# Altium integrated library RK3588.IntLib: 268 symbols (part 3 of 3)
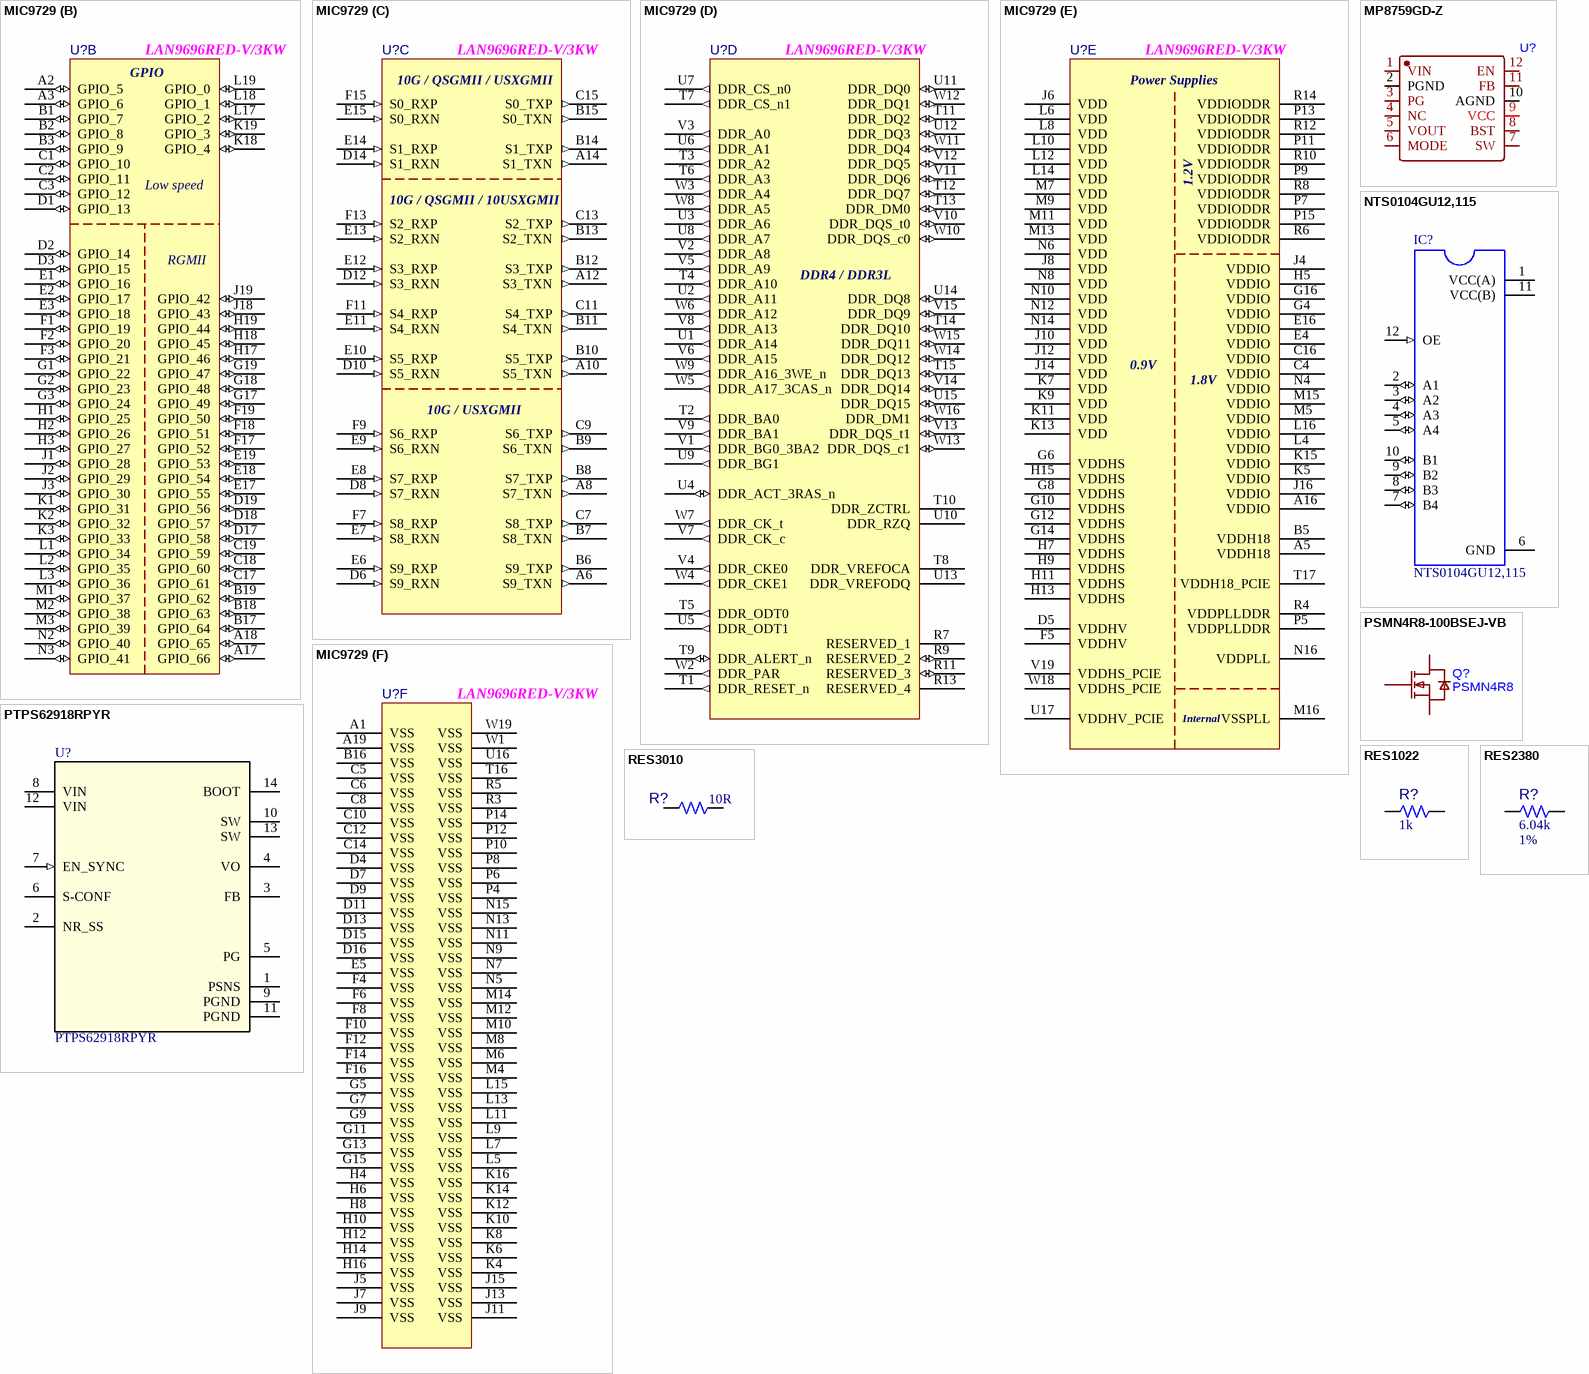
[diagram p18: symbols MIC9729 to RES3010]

## PTPS62918RPYR
designator U?
17V VIN, 8A low-noise low-ripple buck converter with integrated ferrite-bead filter compensation 14-VQFN-HR -40 to 150; Manufacturer_Name: Texas Instruments
footprint RPY0014A-MFG
pins: 1 PSNS, 2 NR_SS, 3 FB, 4 VO, 5 PG (oc), 6 S-CONF, 7 EN_SYNC (in), 8 VIN (power), 9 PGND (power), 10 SW, 11 PGND (power), 12 VIN (power), 13 SW, 14 BOOT

## RES1022
designator R?, comment value 1k  (hidden comment: Resistor)
Manufacturer 1: Panasonic; Manufacturer Part Number 1: ERJ-2RKF1001X; MCHP-ID: RES1022; Tolerance: 1%; Description_: RES TKF 1k 1% 1/10W SMD 0402; Dev Tools Status: Production; Voltage: 50V; Power: 1/10W; Populated: YES; Owner: Tad Ahlvers; Temperature Coefficient: 100ppm/C
footprint RES_C_0402
pins: 1, 2
2 alternate drawings of the same symbol

## RES2380
designator R?, comment value 6.04k  Tolerance: 1%  (hidden comment: Resistor)
Manufacturer 1: Panasonic Electronic Components; Manufacturer Part Number 1: ERJ-2RKF6041X; MCHP-ID: RES2380; Description_: RES TKF 6.04k 1% 1/10W SMD 0402 AEC-Q200; Dev Tools Status: Production; Circuit Type: Isolated; Power: 1/10W; Owner: Steve Dziaba; Populated: YES; Restricted Sourcing: No
footprint RES_C_0402
pins: 1, 2

## RES3010
designator R?, comment value 10R  (hidden comment: Resistor)
Manufacturer 1: Vishay Dale; Manufacturer Part Number 1: CRCW040210R0FKEDC; MCHP-ID: RES3010; Description_: RES TKF 10R 1% 1/16W SMD 0402; Dev Tools Status: Production; Populated: YES; Power: 1/16W; Owner: Balaji Narayana; Tolerance: 1%; Temperature Coefficient: 100ppm/C; Restricted Sourcing: No
footprint RES_C_0402
pins: 1, 2
2 alternate drawings of the same symbol

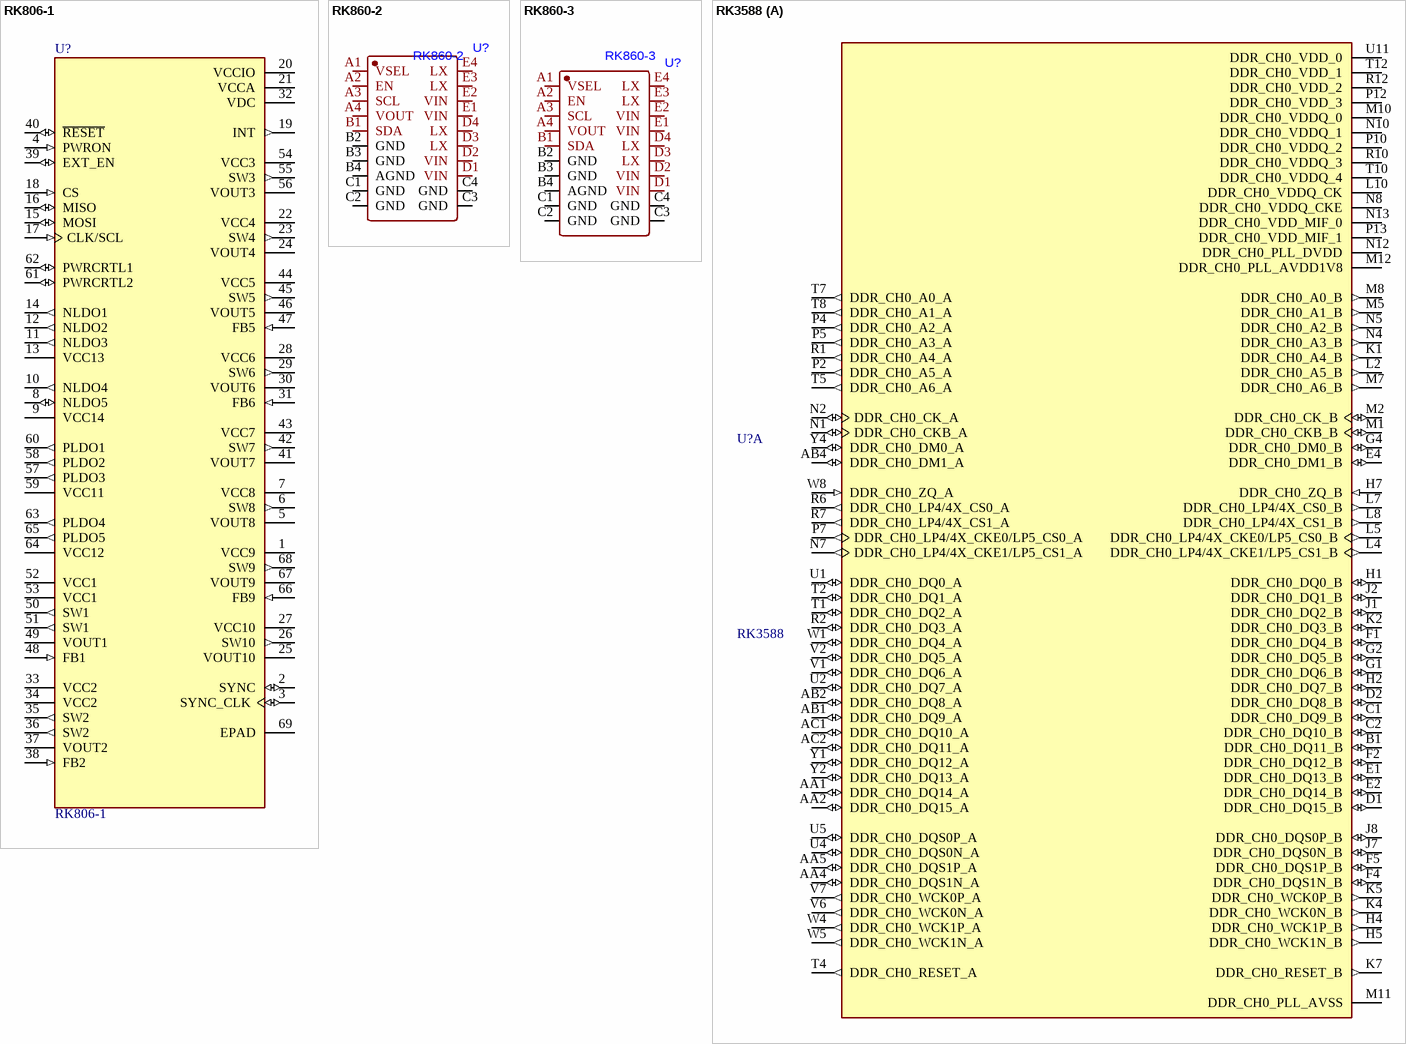
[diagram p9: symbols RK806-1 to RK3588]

## RK806-1
designator U?
RK806-1 Power Management IC; MF: rockchip
footprint QFN35P700X700X90-69N
pins: 1 VCC9 (power), 2 SYNC (io), 3 SYNC_CLK (io), 4 PWRON (in), 5 VOUT8 (power), 6 SW8 (out), 7 VCC8 (power), 8 NLDO5 (io), 9 VCC14 (power), 10 NLDO4 (out), 11 NLDO3 (out), 12 NLDO2 (out), 13 VCC13 (power), 14 NLDO1 (out), 15 MOSI (io), 16 MISO (io), 17 CLK/SCL (in), 18 CS (in), 19 INT (out), 20 VCCIO (power), 21 VCCA (power), 22 VCC4 (power), 23 SW4 (out), 24 VOUT4 (power), 25 VOUT10 (power), 26 SW10 (out), 27 VCC10 (power), 28 VCC6 (power), 29 SW6 (out), 30 VOUT6 (power), 31 FB6 (in), 32 VDC (power), 33 VCC2 (power), 34 VCC2 (power), 35 SW2 (out), 36 SW2 (out), 37 VOUT2 (power), 38 FB2 (in), 39 EXT_EN (io), 40 ~{RESET} (io), 41 VOUT7 (power), 42 SW7 (out), 43 VCC7 (power), 44 VCC5 (power), 45 SW5 (out), 46 VOUT5 (power), 47 FB5 (in), 48 FB1 (in), 49 VOUT1 (power), 50 SW1 (out), 51 SW1 (out), 52 VCC1 (power), 53 VCC1 (power), 54 VCC3 (power), 55 SW3 (out), 56 VOUT3 (power), 57 PLDO3 (out), 58 PLDO2 (out), 59 VCC11 (power), 60 PLDO1 (out), 61 PWRCRTL2 (io), 62 PWRCRTL1 (io), 63 PLDO4 (out), 64 VCC12 (power), 65 PLDO5 (out), 66 FB9 (in), 67 VOUT9 (power), 68 SW9 (out), 69 EPAD

## RK860-2
designator U?
footprint WLCSP-20_L2.0-W1.6-R5-C4-P0.40-TL
pins: A1 VSEL, A2 EN, A3 SCL, A4 VOUT, B1 SDA, B2 GND, B3 GND, B4 AGND, C1 GND, C2 GND, C3 GND, C4 GND, D1 VIN, D2 VIN, D3 LX, D4 LX, E1 VIN, E2 VIN, E3 LX, E4 LX

## RK860-3
designator U?
footprint WLCSP-20_L2.0-W1.6-R5-C4-P0.40-TL
pins: A1 VSEL, A2 EN, A3 SCL, A4 VOUT, B1 SDA, B2 GND, B3 GND, B4 AGND, C1 GND, C2 GND, C3 GND, C4 GND, D1 VIN, D2 VIN, D3 LX, D4 LX, E1 VIN, E2 VIN, E3 LX, E4 LX

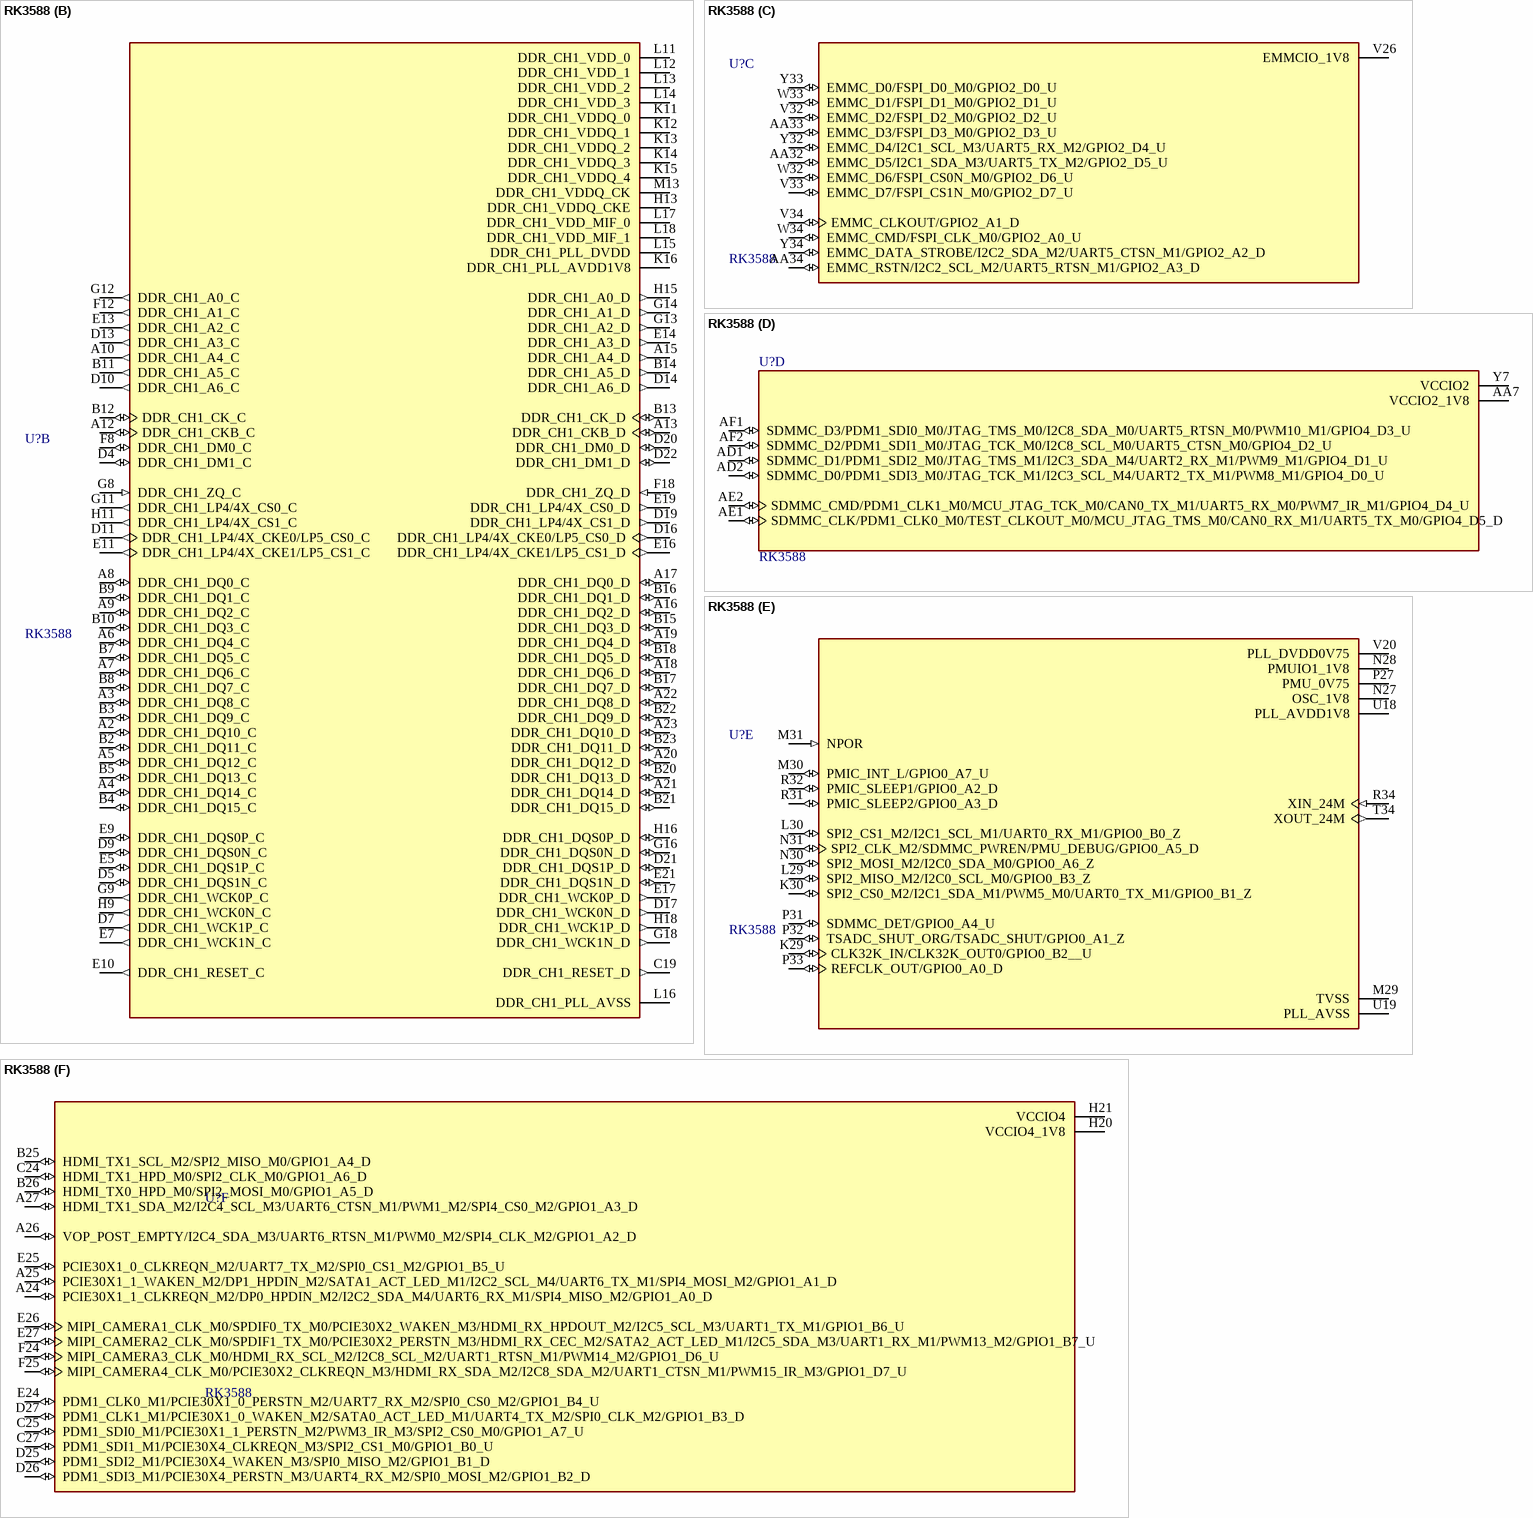
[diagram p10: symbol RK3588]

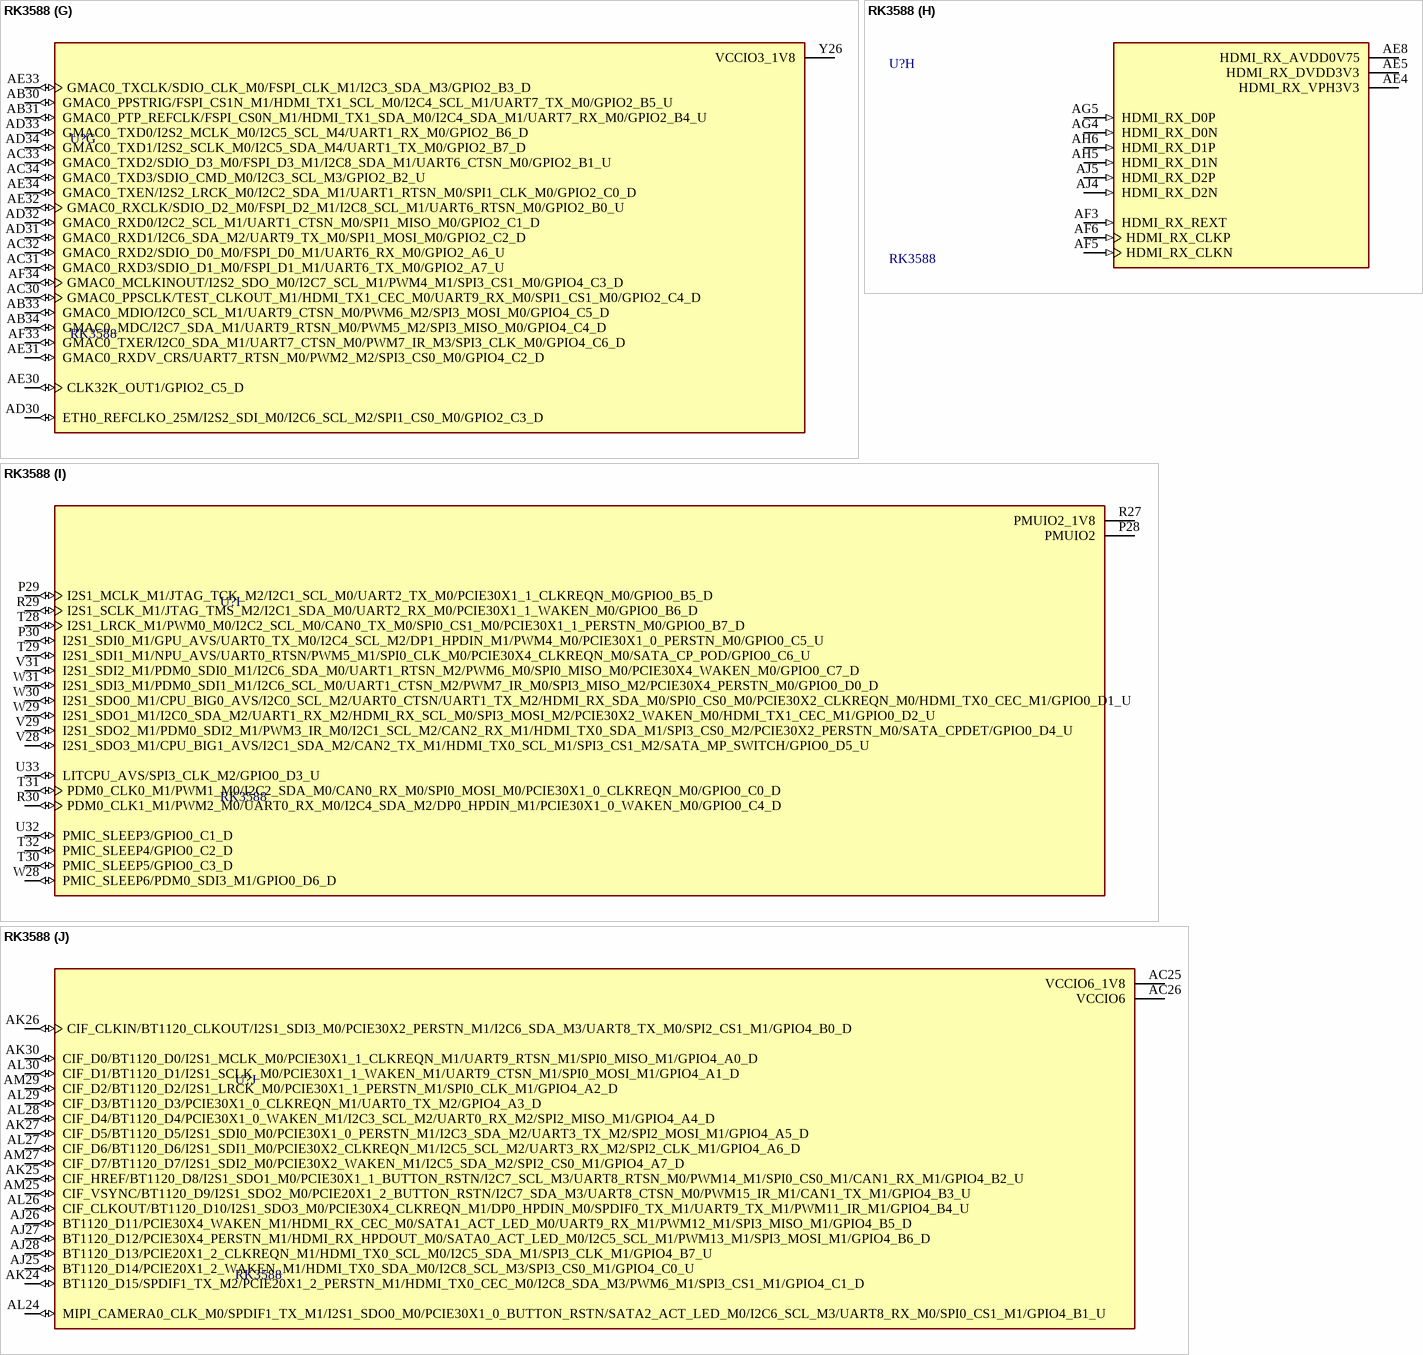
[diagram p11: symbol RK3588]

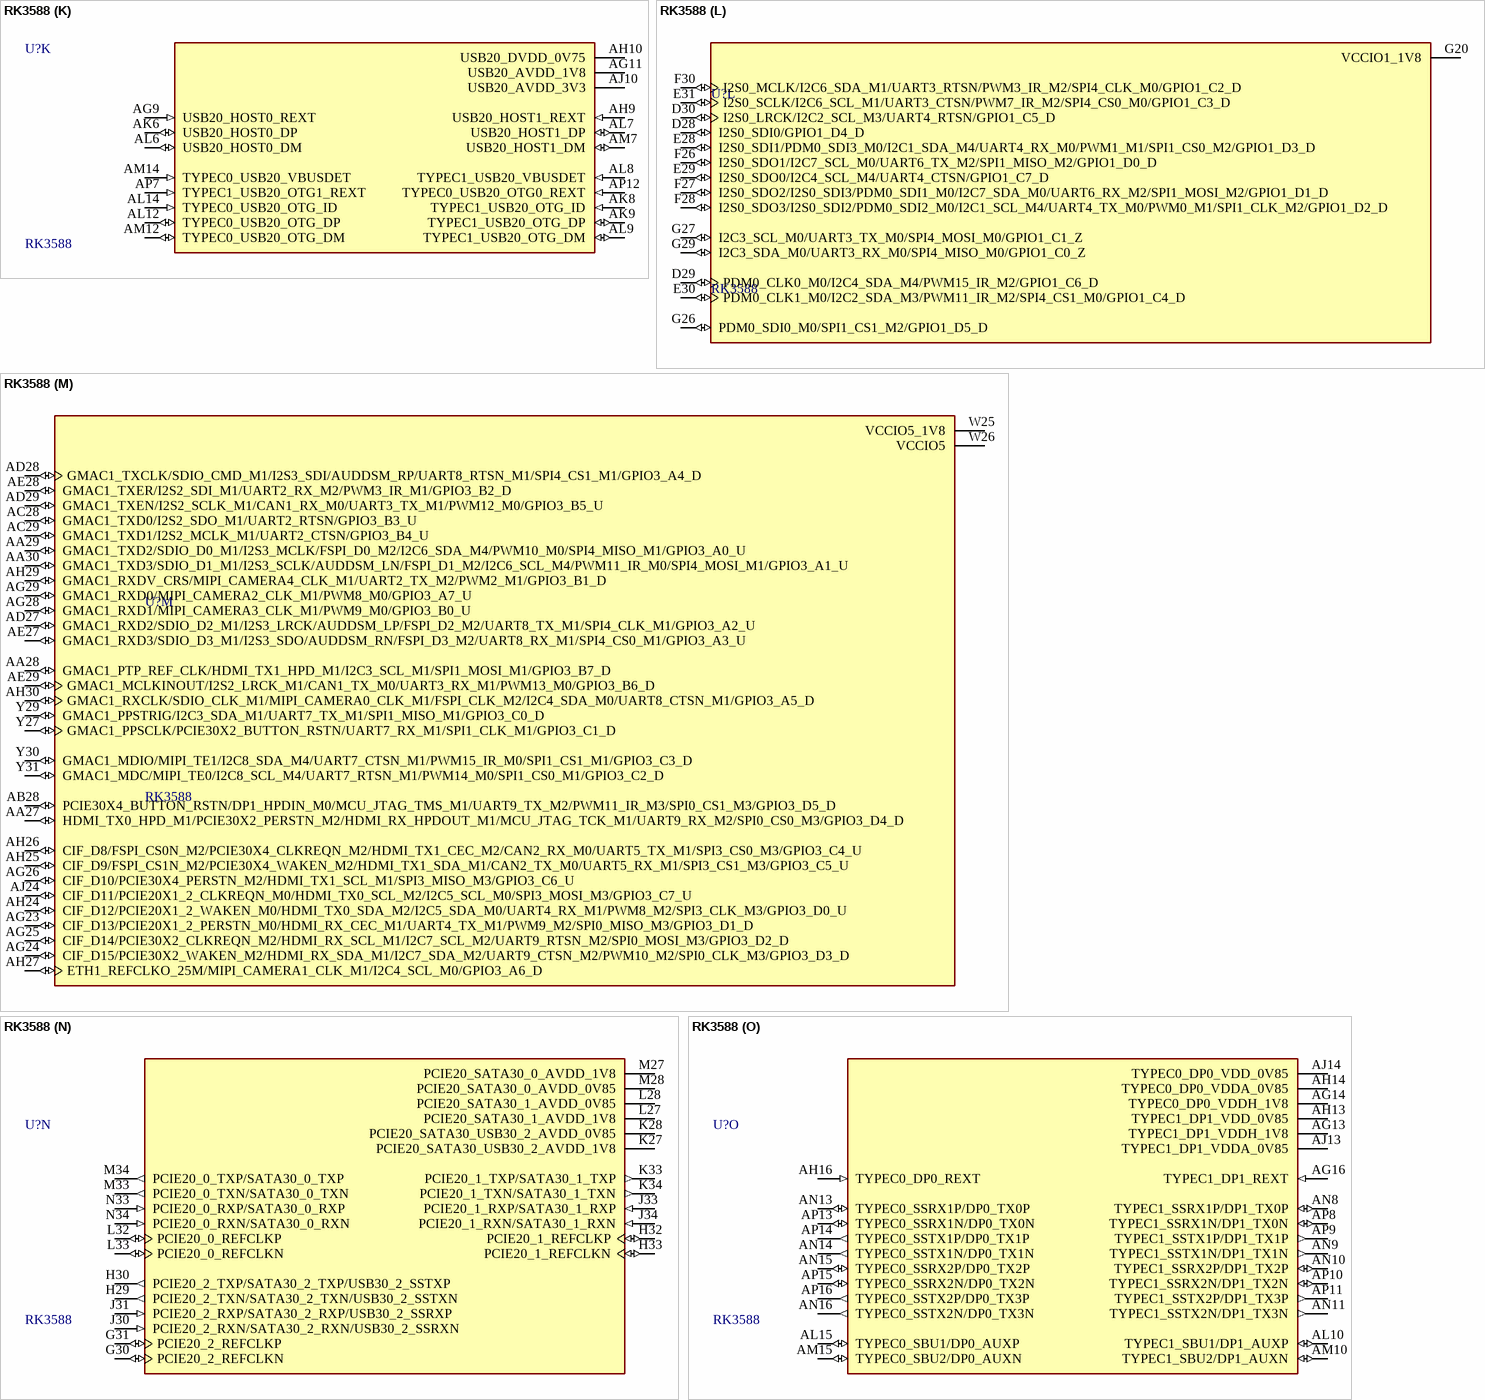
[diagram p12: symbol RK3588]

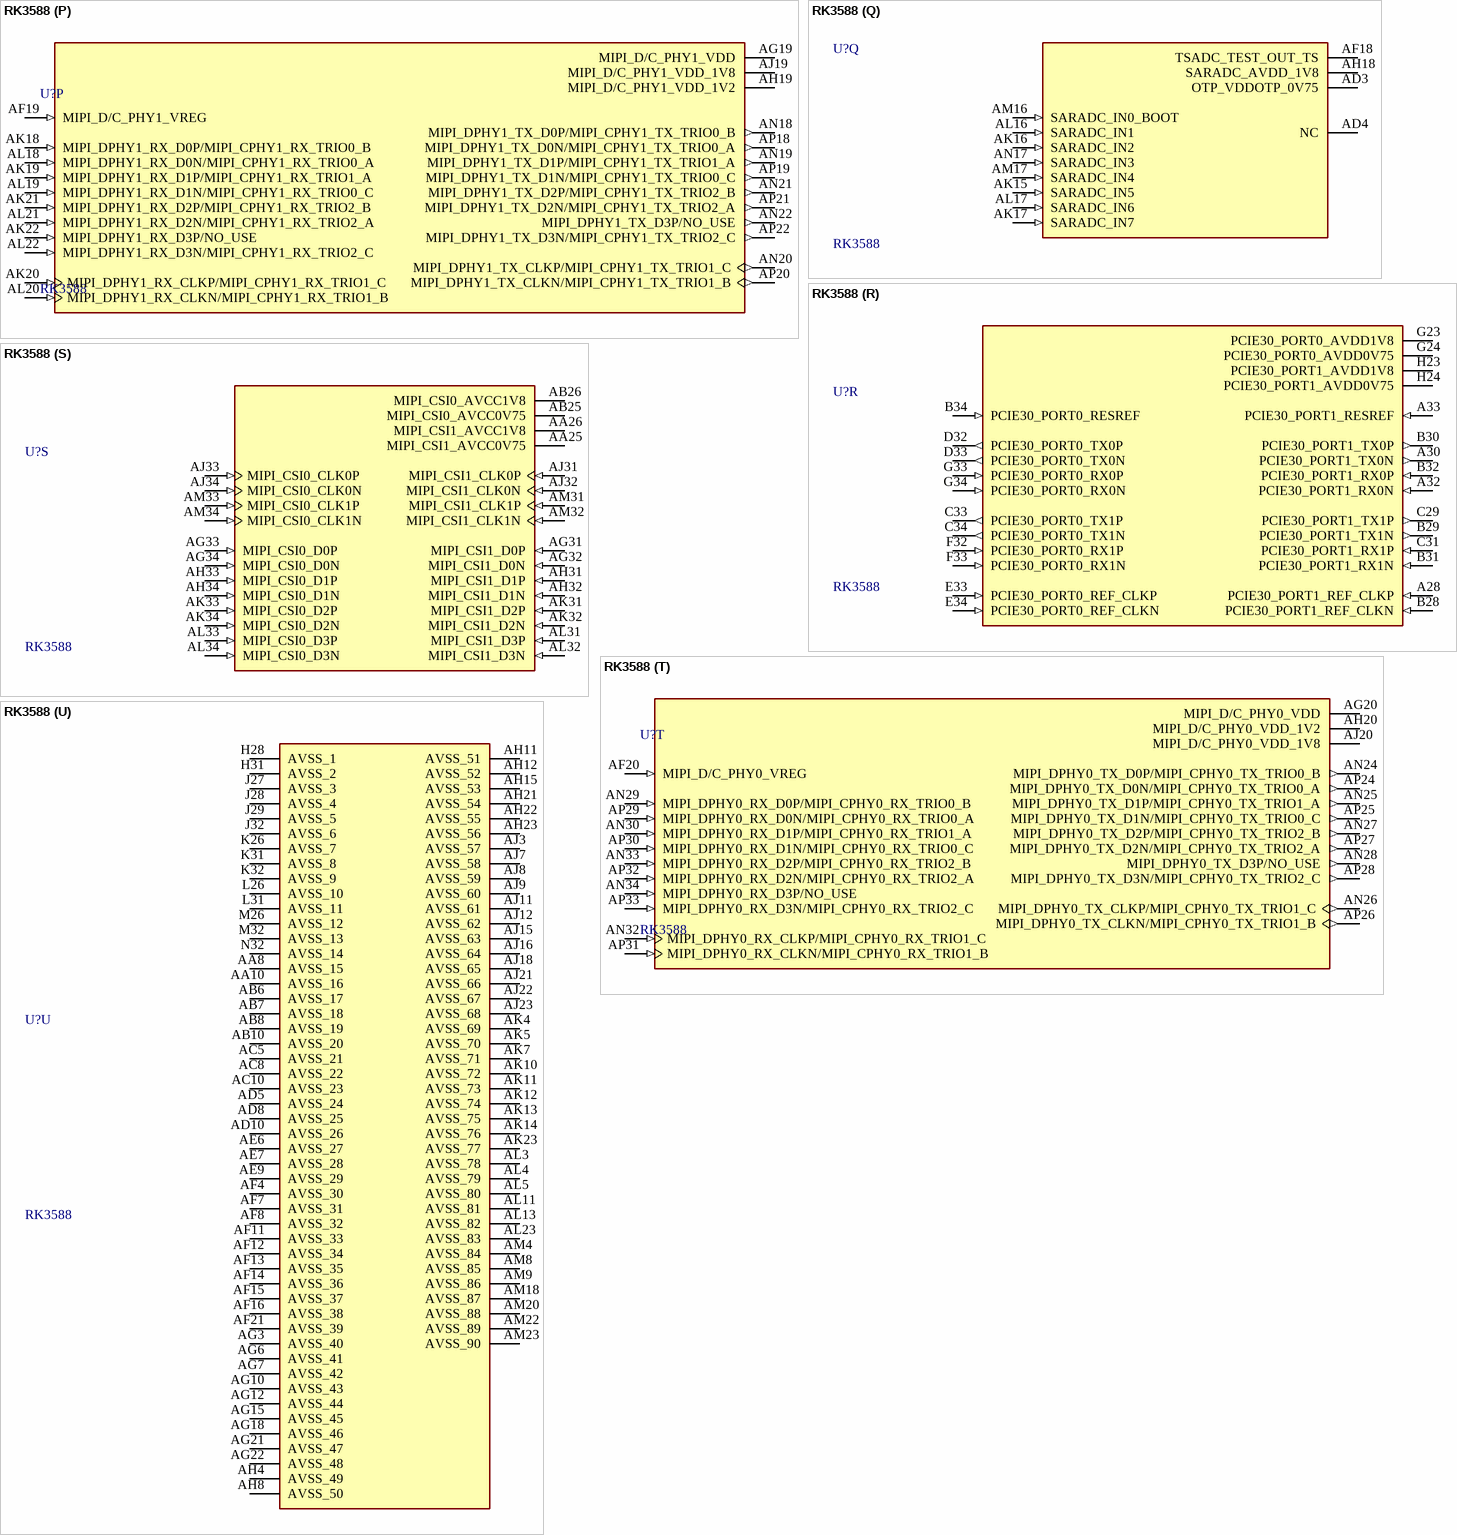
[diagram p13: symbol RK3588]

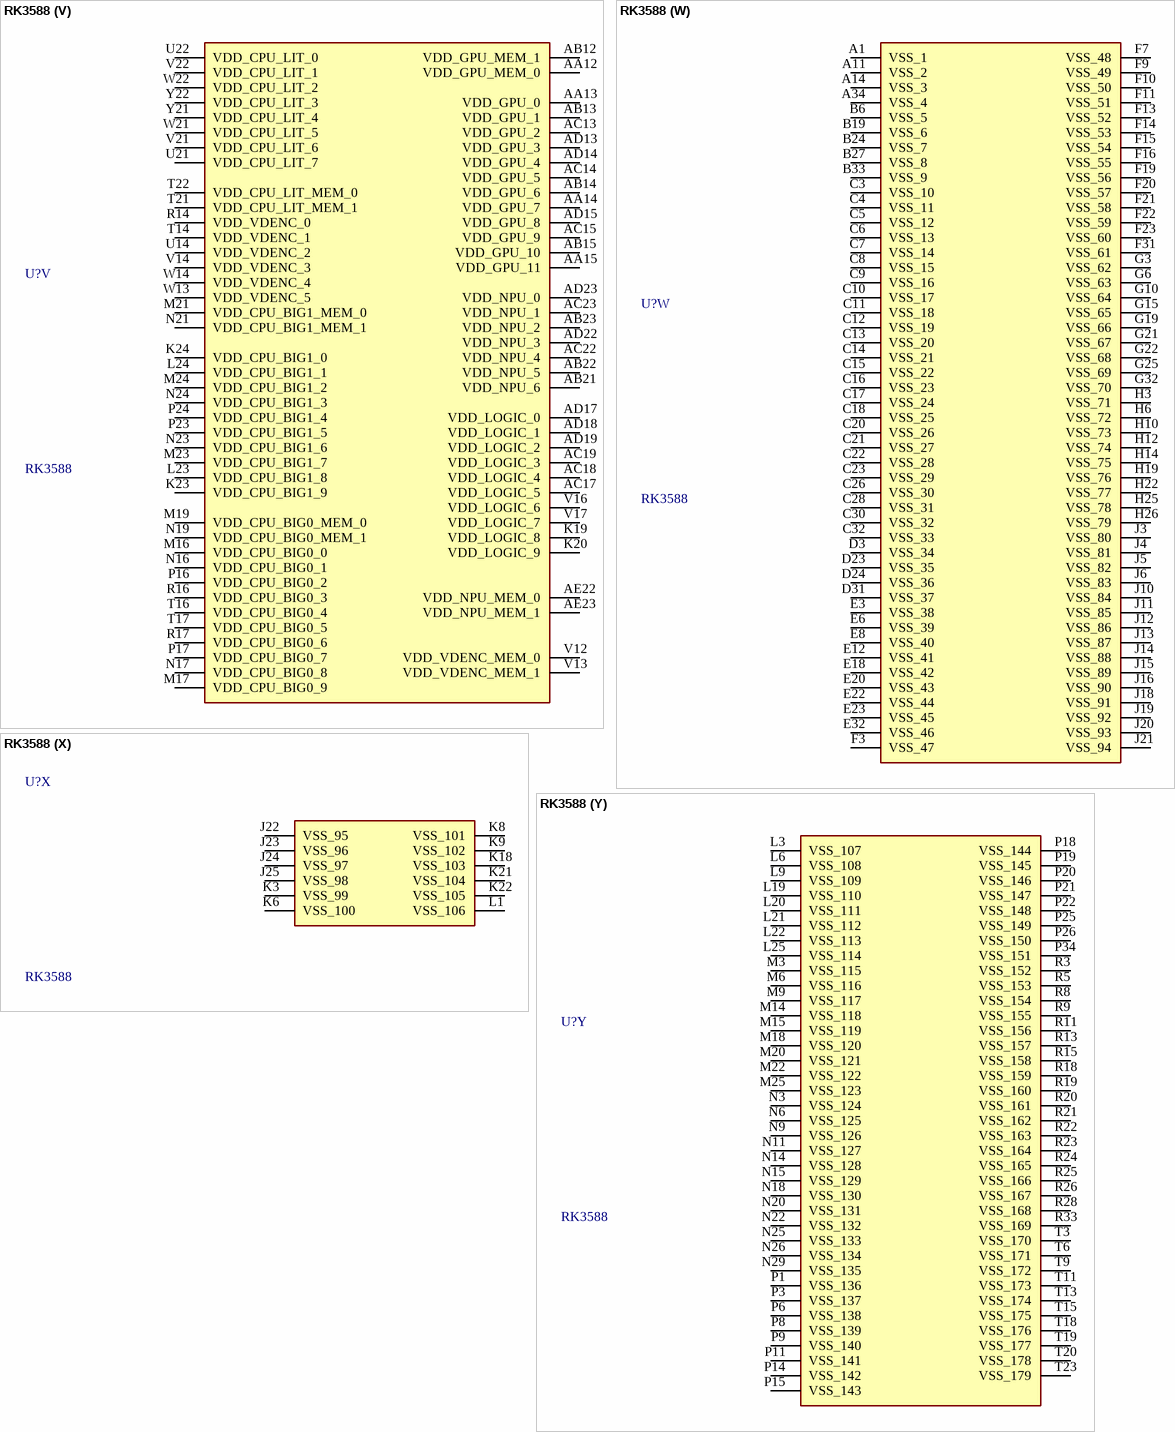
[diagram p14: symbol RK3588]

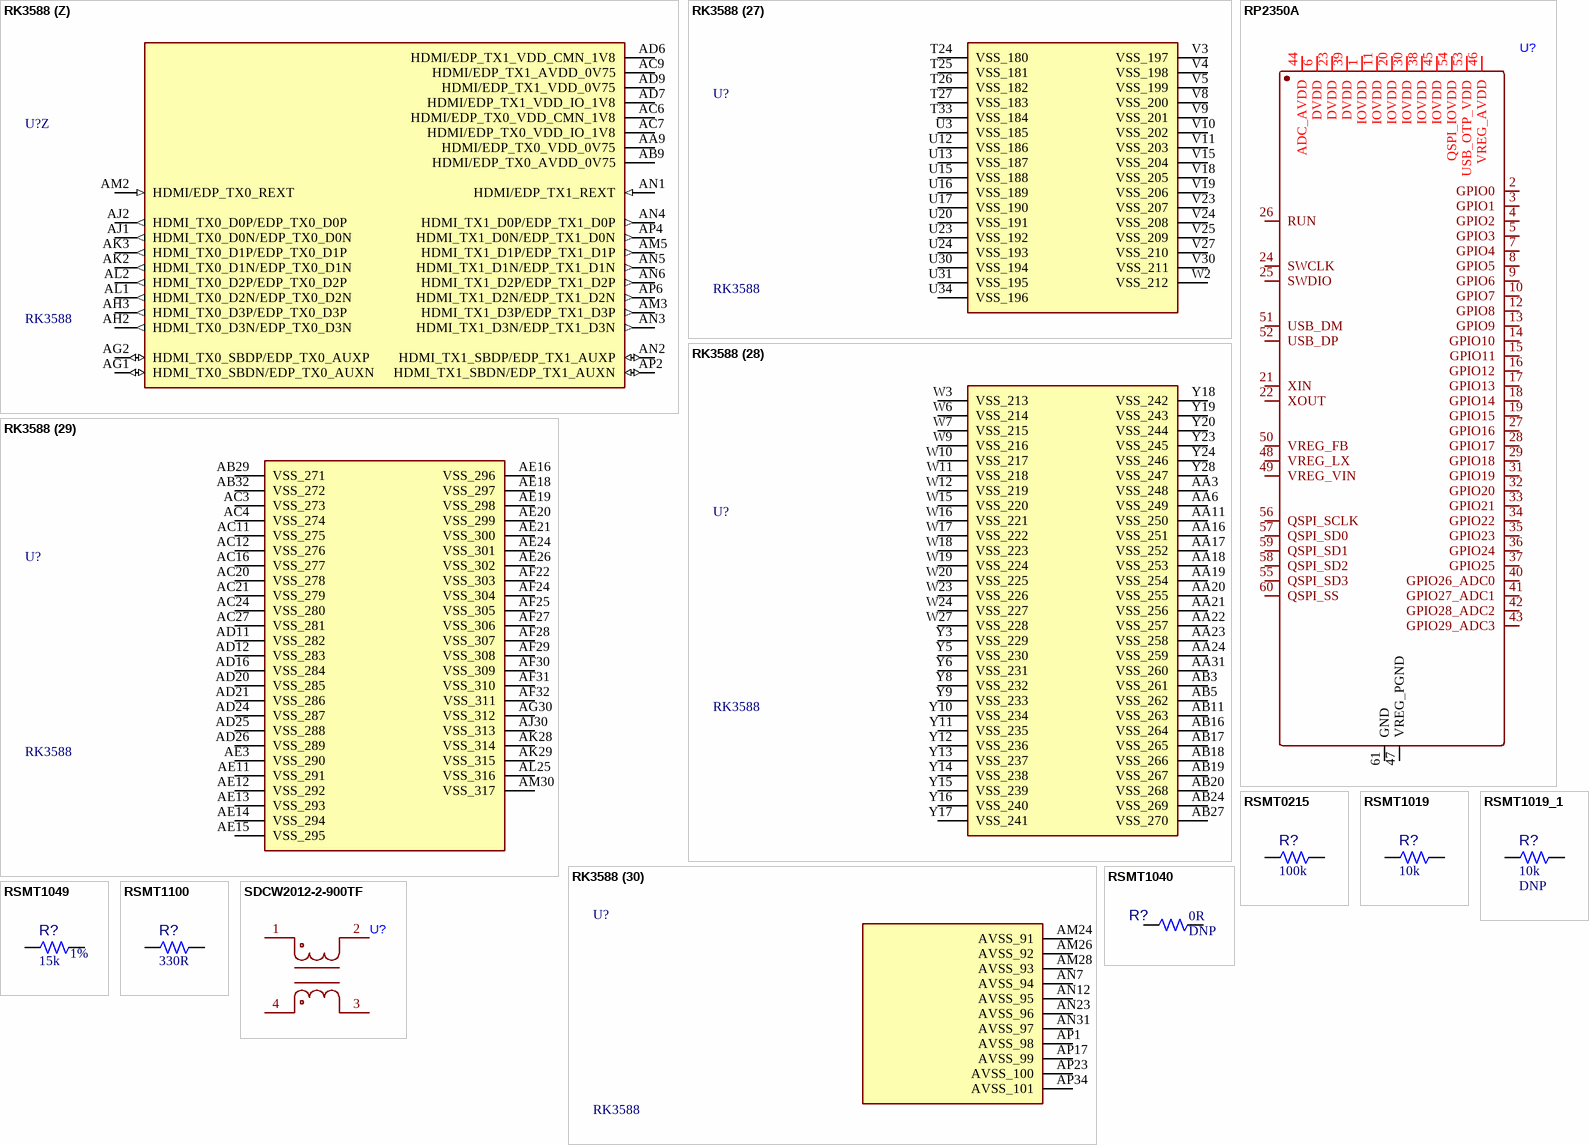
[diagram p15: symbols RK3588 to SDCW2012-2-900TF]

## RK3588
designator U?
low power, high performance processor; MF: Fuzhou Rockchip Electronics Co
footprint BGA1088C65P34X34_2300X2300X204N
part A pins: AA1 DDR_CH0_DQ14_A (io), AA2 DDR_CH0_DQ15_A (io), AA4 DDR_CH0_DQS1N_A (io), AA5 DDR_CH0_DQS1P_A (io), AB1 DDR_CH0_DQ9_A (io), AB2 DDR_CH0_DQ8_A (io), AB4 DDR_CH0_DM1_A (io), AC1 DDR_CH0_DQ10_A (io), AC2 DDR_CH0_DQ11_A (io), B1 DDR_CH0_DQ11_B (io), C1 DDR_CH0_DQ9_B (io), C2 DDR_CH0_DQ10_B (io), D1 DDR_CH0_DQ15_B (io), D2 DDR_CH0_DQ8_B (io), E1 DDR_CH0_DQ13_B (io), E2 DDR_CH0_DQ14_B (io), E4 DDR_CH0_DM1_B (io), F1 DDR_CH0_DQ4_B (io), F2 DDR_CH0_DQ12_B (io), F4 DDR_CH0_DQS1N_B (io), F5 DDR_CH0_DQS1P_B (io), G1 DDR_CH0_DQ6_B (io), G2 DDR_CH0_DQ5_B (io), G4 DDR_CH0_DM0_B (io), H1 DDR_CH0_DQ0_B (io), H2 DDR_CH0_DQ7_B (io), H4 DDR_CH0_WCK1P_B (out), H5 DDR_CH0_WCK1N_B (out), H7 DDR_CH0_ZQ_B (in), J1 DDR_CH0_DQ2_B (io), J2 DDR_CH0_DQ1_B (io), J7 DDR_CH0_DQS0N_B (io), J8 DDR_CH0_DQS0P_B (io), K1 DDR_CH0_A4_B (out), K2 DDR_CH0_DQ3_B (io), K4 DDR_CH0_WCK0N_B (out), K5 DDR_CH0_WCK0P_B (out), K7 DDR_CH0_RESET_B (out), L2 DDR_CH0_A5_B (out), L4 DDR_CH0_LP4/4X_CKE1/LP5_CS1_B (out), L5 DDR_CH0_LP4/4X_CKE0/LP5_CS0_B (out), L7 DDR_CH0_LP4/4X_CS0_B (out), L8 DDR_CH0_LP4/4X_CS1_B (out), L10 DDR_CH0_VDDQ_CK (power), M1 DDR_CH0_CKB_B (io), M2 DDR_CH0_CK_B (io), M5 DDR_CH0_A1_B (out), M7 DDR_CH0_A6_B (out), M8 DDR_CH0_A0_B (out), M10 DDR_CH0_VDDQ_0 (power), M11 DDR_CH0_PLL_AVSS (power), M12 DDR_CH0_PLL_AVDD1V8 (power), N1 DDR_CH0_CKB_A (io), N2 DDR_CH0_CK_A (io), N4 DDR_CH0_A3_B (out), N5 DDR_CH0_A2_B (out), N7 DDR_CH0_LP4/4X_CKE1/LP5_CS1_A (out), N8 DDR_CH0_VDDQ_CKE (power), N10 DDR_CH0_VDDQ_1 (power), N12 DDR_CH0_PLL_DVDD (power), N13 DDR_CH0_VDD_MIF_0 (power), P2 DDR_CH0_A5_A (out), P4 DDR_CH0_A2_A (out), P5 DDR_CH0_A3_A (out), P7 DDR_CH0_LP4/4X_CKE0/LP5_CS0_A (out), P10 DDR_CH0_VDDQ_2 (power), P12 DDR_CH0_VDD_3 (power), P13 DDR_CH0_VDD_MIF_1 (power), R1 DDR_CH0_A4_A (out), R2 DDR_CH0_DQ3_A (io), R6 DDR_CH0_LP4/4X_CS0_A (out), R7 DDR_CH0_LP4/4X_CS1_A (out), R10 DDR_CH0_VDDQ_3 (power), R12 DDR_CH0_VDD_2 (power), T1 DDR_CH0_DQ2_A (io), T2 DDR_CH0_DQ1_A (io), T4 DDR_CH0_RESET_A (out), T5 DDR_CH0_A6_A (out), T7 DDR_CH0_A0_A (out), T8 DDR_CH0_A1_A (out), T10 DDR_CH0_VDDQ_4 (power), T12 DDR_CH0_VDD_1 (power), U1 DDR_CH0_DQ0_A (io), U2 DDR_CH0_DQ7_A (io), U4 DDR_CH0_DQS0N_A (io), U5 DDR_CH0_DQS0P_A (io), U11 DDR_CH0_VDD_0 (power), V1 DDR_CH0_DQ6_A (io), V2 DDR_CH0_DQ5_A (io), V6 DDR_CH0_WCK0N_A (out), V7 DDR_CH0_WCK0P_A (out), W1 DDR_CH0_DQ4_A (io), W4 DDR_CH0_WCK1P_A (out), W5 DDR_CH0_WCK1N_A (out), W8 DDR_CH0_ZQ_A (in), Y1 DDR_CH0_DQ12_A (io), Y2 DDR_CH0_DQ13_A (io), Y4 DDR_CH0_DM0_A (io)
part B pins: A2 DDR_CH1_DQ10_C (io), A3 DDR_CH1_DQ8_C (io), A4 DDR_CH1_DQ14_C (io), A5 DDR_CH1_DQ12_C (io), A6 DDR_CH1_DQ4_C (io), A7 DDR_CH1_DQ6_C (io), A8 DDR_CH1_DQ0_C (io), A9 DDR_CH1_DQ2_C (io), A10 DDR_CH1_A4_C (out), A12 DDR_CH1_CKB_C (io), A13 DDR_CH1_CKB_D (io), A15 DDR_CH1_A4_D (out), A16 DDR_CH1_DQ2_D (io), A17 DDR_CH1_DQ0_D (io), A18 DDR_CH1_DQ6_D (io), A19 DDR_CH1_DQ4_D (io), A20 DDR_CH1_DQ12_D (io), A21 DDR_CH1_DQ14_D (io), A22 DDR_CH1_DQ8_D (io), A23 DDR_CH1_DQ10_D (io), B2 DDR_CH1_DQ11_C (io), B3 DDR_CH1_DQ9_C (io), B4 DDR_CH1_DQ15_C (io), B5 DDR_CH1_DQ13_C (io), B7 DDR_CH1_DQ5_C (io), B8 DDR_CH1_DQ7_C (io), B9 DDR_CH1_DQ1_C (io), B10 DDR_CH1_DQ3_C (io), B11 DDR_CH1_A5_C (out), B12 DDR_CH1_CK_C (io), B13 DDR_CH1_CK_D (io), B14 DDR_CH1_A5_D (out), B15 DDR_CH1_DQ3_D (io), B16 DDR_CH1_DQ1_D (io), B17 DDR_CH1_DQ7_D (io), B18 DDR_CH1_DQ5_D (io), B20 DDR_CH1_DQ13_D (io), B21 DDR_CH1_DQ15_D (io), B22 DDR_CH1_DQ9_D (io), B23 DDR_CH1_DQ11_D (io), C19 DDR_CH1_RESET_D (out), D4 DDR_CH1_DM1_C (io), D5 DDR_CH1_DQS1N_C (io), D7 DDR_CH1_WCK1P_C (out), D9 DDR_CH1_DQS0N_C (io), D10 DDR_CH1_A6_C (out), D11 DDR_CH1_LP4/4X_CKE0/LP5_CS0_C (out), D13 DDR_CH1_A3_C (out), D14 DDR_CH1_A6_D (out), D16 DDR_CH1_LP4/4X_CKE0/LP5_CS0_D (out), D17 DDR_CH1_WCK0N_D (out), D19 DDR_CH1_LP4/4X_CS1_D (out), D20 DDR_CH1_DM0_D (io), D21 DDR_CH1_DQS1P_D (io), D22 DDR_CH1_DM1_D (io), E5 DDR_CH1_DQS1P_C (io), E7 DDR_CH1_WCK1N_C (out), E9 DDR_CH1_DQS0P_C (io), E10 DDR_CH1_RESET_C (out), E11 DDR_CH1_LP4/4X_CKE1/LP5_CS1_C (out), E13 DDR_CH1_A2_C (out), E14 DDR_CH1_A3_D (out), E16 DDR_CH1_LP4/4X_CKE1/LP5_CS1_D (out), E17 DDR_CH1_WCK0P_D (out), E19 DDR_CH1_LP4/4X_CS0_D (out), E21 DDR_CH1_DQS1N_D (io), F8 DDR_CH1_DM0_C (io), F12 DDR_CH1_A1_C (out), F18 DDR_CH1_ZQ_D (in), G8 DDR_CH1_ZQ_C (in), G9 DDR_CH1_WCK0P_C (out), G11 DDR_CH1_LP4/4X_CS0_C (out), G12 DDR_CH1_A0_C (out), G13 DDR_CH1_A2_D (out), G14 DDR_CH1_A1_D (out), G16 DDR_CH1_DQS0N_D (io), G18 DDR_CH1_WCK1N_D (out), H9 DDR_CH1_WCK0N_C (out), H11 DDR_CH1_LP4/4X_CS1_C (out), H13 DDR_CH1_VDDQ_CKE (power), H15 DDR_CH1_A0_D (out), H16 DDR_CH1_DQS0P_D (io), H18 DDR_CH1_WCK1P_D (out), K11 DDR_CH1_VDDQ_0 (power), K12 DDR_CH1_VDDQ_1 (power), K13 DDR_CH1_VDDQ_2 (power), K14 DDR_CH1_VDDQ_3 (power), K15 DDR_CH1_VDDQ_4 (power), K16 DDR_CH1_PLL_AVDD1V8 (power), L11 DDR_CH1_VDD_0 (power), L12 DDR_CH1_VDD_1 (power), L13 DDR_CH1_VDD_2 (power), L14 DDR_CH1_VDD_3 (power), L15 DDR_CH1_PLL_DVDD (power), L16 DDR_CH1_PLL_AVSS (power), L17 DDR_CH1_VDD_MIF_0 (power), L18 DDR_CH1_VDD_MIF_1 (power), M13 DDR_CH1_VDDQ_CK (power)
part C pins: AA32 EMMC_D5/I2C1_SDA_M3/UART5_TX_M2/GPIO2_D5_U (io), AA33 EMMC_D3/FSPI_D3_M0/GPIO2_D3_U (io), AA34 EMMC_RSTN/I2C2_SCL_M2/UART5_RTSN_M1/GPIO2_A3_D (io), V26 EMMCIO_1V8 (power), V32 EMMC_D2/FSPI_D2_M0/GPIO2_D2_U (io), V33 EMMC_D7/FSPI_CS1N_M0/GPIO2_D7_U (io), V34 EMMC_CLKOUT/GPIO2_A1_D (io), W32 EMMC_D6/FSPI_CS0N_M0/GPIO2_D6_U (io), W33 EMMC_D1/FSPI_D1_M0/GPIO2_D1_U (io), W34 EMMC_CMD/FSPI_CLK_M0/GPIO2_A0_U (io), Y32 EMMC_D4/I2C1_SCL_M3/UART5_RX_M2/GPIO2_D4_U (io), Y33 EMMC_D0/FSPI_D0_M0/GPIO2_D0_U (io), Y34 EMMC_DATA_STROBE/I2C2_SDA_M2/UART5_CTSN_M1/GPIO2_A2_D (io)
part D pins: AA7 VCCIO2_1V8 (power), AD1 SDMMC_D1/PDM1_SDI2_M0/JTAG_TMS_M1/I2C3_SDA_M4/UART2_RX_M1/PWM9_M1/GPIO4_D1_U (io), AD2 SDMMC_D0/PDM1_SDI3_M0/JTAG_TCK_M1/I2C3_SCL_M4/UART2_TX_M1/PWM8_M1/GPIO4_D0_U (io), AE1 SDMMC_CLK/PDM1_CLK0_M0/TEST_CLKOUT_M0/MCU_JTAG_TMS_M0/CAN0_RX_M1/UART5_TX_M0/GPIO4_D5_D (io), AE2 SDMMC_CMD/PDM1_CLK1_M0/MCU_JTAG_TCK_M0/CAN0_TX_M1/UART5_RX_M0/PWM7_IR_M1/GPIO4_D4_U (io), AF1 SDMMC_D3/PDM1_SDI0_M0/JTAG_TMS_M0/I2C8_SDA_M0/UART5_RTSN_M0/PWM10_M1/GPIO4_D3_U (io), AF2 SDMMC_D2/PDM1_SDI1_M0/JTAG_TCK_M0/I2C8_SCL_M0/UART5_CTSN_M0/GPIO4_D2_U (io), Y7 VCCIO2 (power)
part E pins: K29 CLK32K_IN/CLK32K_OUT0/GPIO0_B2__U (io), K30 SPI2_CS0_M2/I2C1_SDA_M1/PWM5_M0/UART0_TX_M1/GPIO0_B1_Z (io), L29 SPI2_MISO_M2/I2C0_SCL_M0/GPIO0_B3_Z (io), L30 SPI2_CS1_M2/I2C1_SCL_M1/UART0_RX_M1/GPIO0_B0_Z (io), M29 TVSS (power), M30 PMIC_INT_L/GPIO0_A7_U (io), M31 NPOR (in), N27 OSC_1V8 (power), N28 PMUIO1_1V8 (power), N30 SPI2_MOSI_M2/I2C0_SDA_M0/GPIO0_A6_Z (io), N31 SPI2_CLK_M2/SDMMC_PWREN/PMU_DEBUG/GPIO0_A5_D (io), P27 PMU_0V75 (power), P31 SDMMC_DET/GPIO0_A4_U (io), P32 TSADC_SHUT_ORG/TSADC_SHUT/GPIO0_A1_Z (io), P33 REFCLK_OUT/GPIO0_A0_D (io), R31 PMIC_SLEEP2/GPIO0_A3_D (io), R32 PMIC_SLEEP1/GPIO0_A2_D (io), R34 XIN_24M (in), T34 XOUT_24M (out), U18 PLL_AVDD1V8 (power), U19 PLL_AVSS (power), V20 PLL_DVDD0V75 (power)
part F pins: A24 PCIE30X1_1_CLKREQN_M2/DP0_HPDIN_M2/I2C2_SDA_M4/UART6_RX_M1/SPI4_MISO_M2/GPIO1_A0_D (io), A25 PCIE30X1_1_WAKEN_M2/DP1_HPDIN_M2/SATA1_ACT_LED_M1/I2C2_SCL_M4/UART6_TX_M1/SPI4_MOSI_M2/GPIO1_A1_D (io), A26 VOP_POST_EMPTY/I2C4_SDA_M3/UART6_RTSN_M1/PWM0_M2/SPI4_CLK_M2/GPIO1_A2_D (io), A27 HDMI_TX1_SDA_M2/I2C4_SCL_M3/UART6_CTSN_M1/PWM1_M2/SPI4_CS0_M2/GPIO1_A3_D (io), B25 HDMI_TX1_SCL_M2/SPI2_MISO_M0/GPIO1_A4_D (io), B26 HDMI_TX0_HPD_M0/SPI2_MOSI_M0/GPIO1_A5_D (io), C24 HDMI_TX1_HPD_M0/SPI2_CLK_M0/GPIO1_A6_D (io), C25 PDM1_SDI0_M1/PCIE30X1_1_PERSTN_M2/PWM3_IR_M3/SPI2_CS0_M0/GPIO1_A7_U (io), C27 PDM1_SDI1_M1/PCIE30X4_CLKREQN_M3/SPI2_CS1_M0/GPIO1_B0_U (io), D25 PDM1_SDI2_M1/PCIE30X4_WAKEN_M3/SPI0_MISO_M2/GPIO1_B1_D (io), D26 PDM1_SDI3_M1/PCIE30X4_PERSTN_M3/UART4_RX_M2/SPI0_MOSI_M2/GPIO1_B2_D (io), D27 PDM1_CLK1_M1/PCIE30X1_0_WAKEN_M2/SATA0_ACT_LED_M1/UART4_TX_M2/SPI0_CLK_M2/GPIO1_B3_D (io), E24 PDM1_CLK0_M1/PCIE30X1_0_PERSTN_M2/UART7_RX_M2/SPI0_CS0_M2/GPIO1_B4_U (io), E25 PCIE30X1_0_CLKREQN_M2/UART7_TX_M2/SPI0_CS1_M2/GPIO1_B5_U (io), E26 MIPI_CAMERA1_CLK_M0/SPDIF0_TX_M0/PCIE30X2_WAKEN_M3/HDMI_RX_HPDOUT_M2/I2C5_SCL_M3/UART1_TX_M1/GPIO1_B6_U (io), E27 MIPI_CAMERA2_CLK_M0/SPDIF1_TX_M0/PCIE30X2_PERSTN_M3/HDMI_RX_CEC_M2/SATA2_ACT_LED_M1/I2C5_SDA_M3/UART1_RX_M1/PWM13_M2/GPIO1_B7_U (io), F24 MIPI_CAMERA3_CLK_M0/HDMI_RX_SCL_M2/I2C8_SCL_M2/UART1_RTSN_M1/PWM14_M2/GPIO1_D6_U (io), F25 MIPI_CAMERA4_CLK_M0/PCIE30X2_CLKREQN_M3/HDMI_RX_SDA_M2/I2C8_SDA_M2/UART1_CTSN_M1/PWM15_IR_M3/GPIO1_D7_U (io), H20 VCCIO4_1V8 (power), H21 VCCIO4 (power)
part G pins: AB30 GMAC0_PPSTRIG/FSPI_CS1N_M1/HDMI_TX1_SCL_M0/I2C4_SCL_M1/UART7_TX_M0/GPIO2_B5_U (io), AB31 GMAC0_PTP_REFCLK/FSPI_CS0N_M1/HDMI_TX1_SDA_M0/I2C4_SDA_M1/UART7_RX_M0/GPIO2_B4_U (io), AB33 GMAC0_MDIO/I2C0_SCL_M1/UART9_CTSN_M0/PWM6_M2/SPI3_MOSI_M0/GPIO4_C5_D (io), AB34 GMAC0_MDC/I2C7_SDA_M1/UART9_RTSN_M0/PWM5_M2/SPI3_MISO_M0/GPIO4_C4_D (io), AC30 GMAC0_PPSCLK/TEST_CLKOUT_M1/HDMI_TX1_CEC_M0/UART9_RX_M0/SPI1_CS1_M0/GPIO2_C4_D (io), AC31 GMAC0_RXD3/SDIO_D1_M0/FSPI_D1_M1/UART6_TX_M0/GPIO2_A7_U (io), AC32 GMAC0_RXD2/SDIO_D0_M0/FSPI_D0_M1/UART6_RX_M0/GPIO2_A6_U (io), AC33 GMAC0_TXD2/SDIO_D3_M0/FSPI_D3_M1/I2C8_SDA_M1/UART6_CTSN_M0/GPIO2_B1_U (io), AC34 GMAC0_TXD3/SDIO_CMD_M0/I2C3_SCL_M3/GPIO2_B2_U (io), AD30 ETH0_REFCLKO_25M/I2S2_SDI_M0/I2C6_SCL_M2/SPI1_CS0_M0/GPIO2_C3_D (io), AD31 GMAC0_RXD1/I2C6_SDA_M2/UART9_TX_M0/SPI1_MOSI_M0/GPIO2_C2_D (io), AD32 GMAC0_RXD0/I2C2_SCL_M1/UART1_CTSN_M0/SPI1_MISO_M0/GPIO2_C1_D (io), AD33 GMAC0_TXD0/I2S2_MCLK_M0/I2C5_SCL_M4/UART1_RX_M0/GPIO2_B6_D (io), AD34 GMAC0_TXD1/I2S2_SCLK_M0/I2C5_SDA_M4/UART1_TX_M0/GPIO2_B7_D (io), AE30 CLK32K_OUT1/GPIO2_C5_D (io), AE31 GMAC0_RXDV_CRS/UART7_RTSN_M0/PWM2_M2/SPI3_CS0_M0/GPIO4_C2_D (io), AE32 GMAC0_RXCLK/SDIO_D2_M0/FSPI_D2_M1/I2C8_SCL_M1/UART6_RTSN_M0/GPIO2_B0_U (io), AE33 GMAC0_TXCLK/SDIO_CLK_M0/FSPI_CLK_M1/I2C3_SDA_M3/GPIO2_B3_D (io), AE34 GMAC0_TXEN/I2S2_LRCK_M0/I2C2_SDA_M1/UART1_RTSN_M0/SPI1_CLK_M0/GPIO2_C0_D (io), AF33 GMAC0_TXER/I2C0_SDA_M1/UART7_CTSN_M0/PWM7_IR_M3/SPI3_CLK_M0/GPIO4_C6_D (io), AF34 GMAC0_MCLKINOUT/I2S2_SDO_M0/I2C7_SCL_M1/PWM4_M1/SPI3_CS1_M0/GPIO4_C3_D (io), Y26 VCCIO3_1V8 (power)
part H pins: AE4 HDMI_RX_VPH3V3 (power), AE5 HDMI_RX_DVDD3V3 (power), AE8 HDMI_RX_AVDD0V75 (power), AF3 HDMI_RX_REXT (in), AF5 HDMI_RX_CLKN (in), AF6 HDMI_RX_CLKP (in), AG4 HDMI_RX_D0N (in), AG5 HDMI_RX_D0P (in), AH5 HDMI_RX_D1N (in), AH6 HDMI_RX_D1P (in), AJ4 HDMI_RX_D2N (in), AJ5 HDMI_RX_D2P (in)
part I pins: P28 PMUIO2 (power), P29 I2S1_MCLK_M1/JTAG_TCK_M2/I2C1_SCL_M0/UART2_TX_M0/PCIE30X1_1_CLKREQN_M0/GPIO0_B5_D (io), P30 I2S1_SDI0_M1/GPU_AVS/UART0_TX_M0/I2C4_SCL_M2/DP1_HPDIN_M1/PWM4_M0/PCIE30X1_0_PERSTN_M0/GPIO0_C5_U (io), R27 PMUIO2_1V8 (power), R29 I2S1_SCLK_M1/JTAG_TMS_M2/I2C1_SDA_M0/UART2_RX_M0/PCIE30X1_1_WAKEN_M0/GPIO0_B6_D (io), R30 PDM0_CLK1_M1/PWM2_M0/UART0_RX_M0/I2C4_SDA_M2/DP0_HPDIN_M1/PCIE30X1_0_WAKEN_M0/GPIO0_C4_D (io), T28 I2S1_LRCK_M1/PWM0_M0/I2C2_SCL_M0/CAN0_TX_M0/SPI0_CS1_M0/PCIE30X1_1_PERSTN_M0/GPIO0_B7_D (io), T29 I2S1_SDI1_M1/NPU_AVS/UART0_RTSN/PWM5_M1/SPI0_CLK_M0/PCIE30X4_CLKREQN_M0/SATA_CP_POD/GPIO0_C6_U (io), T30 PMIC_SLEEP5/GPIO0_C3_D (io), T31 PDM0_CLK0_M1/PWM1_M0/I2C2_SDA_M0/CAN0_RX_M0/SPI0_MOSI_M0/PCIE30X1_0_CLKREQN_M0/GPIO0_C0_D (io), T32 PMIC_SLEEP4/GPIO0_C2_D (io), U32 PMIC_SLEEP3/GPIO0_C1_D (io), U33 LITCPU_AVS/SPI3_CLK_M2/GPIO0_D3_U (io), V28 I2S1_SDO3_M1/CPU_BIG1_AVS/I2C1_SDA_M2/CAN2_TX_M1/HDMI_TX0_SCL_M1/SPI3_CS1_M2/SATA_MP_SWITCH/GPIO0_D5_U (io), V29 I2S1_SDO2_M1/PDM0_SDI2_M1/PWM3_IR_M0/I2C1_SCL_M2/CAN2_RX_M1/HDMI_TX0_SDA_M1/SPI3_CS0_M2/PCIE30X2_PERSTN_M0/SATA_CPDET/GPIO0_D4_U (io), V31 I2S1_SDI2_M1/PDM0_SDI0_M1/I2C6_SDA_M0/UART1_RTSN_M2/PWM6_M0/SPI0_MISO_M0/PCIE30X4_WAKEN_M0/GPIO0_C7_D (io), W28 PMIC_SLEEP6/PDM0_SDI3_M1/GPIO0_D6_D (io), W29 I2S1_SDO1_M1/I2C0_SDA_M2/UART1_RX_M2/HDMI_RX_SCL_M0/SPI3_MOSI_M2/PCIE30X2_WAKEN_M0/HDMI_TX1_CEC_M1/GPIO0_D2_U (io), W30 I2S1_SDO0_M1/CPU_BIG0_AVS/I2C0_SCL_M2/UART0_CTSN/UART1_TX_M2/HDMI_RX_SDA_M0/SPI0_CS0_M0/PCIE30X2_CLKREQN_M0/HDMI_TX0_CEC_M1/GPIO0_D1_U (io), W31 I2S1_SDI3_M1/PDM0_SDI1_M1/I2C6_SCL_M0/UART1_CTSN_M2/PWM7_IR_M0/SPI3_MISO_M2/PCIE30X4_PERSTN_M0/GPIO0_D0_D (io)
part J pins: AC25 VCCIO6_1V8 (power), AC26 VCCIO6 (power), AJ25 BT1120_D14/PCIE20X1_2_WAKEN_M1/HDMI_TX0_SDA_M0/I2C8_SCL_M3/SPI3_CS0_M1/GPIO4_C0_U (io), AJ26 BT1120_D11/PCIE30X4_WAKEN_M1/HDMI_RX_CEC_M0/SATA1_ACT_LED_M0/UART9_RX_M1/PWM12_M1/SPI3_MISO_M1/GPIO4_B5_D (io), AJ27 BT1120_D12/PCIE30X4_PERSTN_M1/HDMI_RX_HPDOUT_M0/SATA0_ACT_LED_M0/I2C5_SCL_M1/PWM13_M1/SPI3_MOSI_M1/GPIO4_B6_D (io), AJ28 BT1120_D13/PCIE20X1_2_CLKREQN_M1/HDMI_TX0_SCL_M0/I2C5_SDA_M1/SPI3_CLK_M1/GPIO4_B7_U (io), AK24 BT1120_D15/SPDIF1_TX_M2/PCIE20X1_2_PERSTN_M1/HDMI_TX0_CEC_M0/I2C8_SDA_M3/PWM6_M1/SPI3_CS1_M1/GPIO4_C1_D (io), AK25 CIF_HREF/BT1120_D8/I2S1_SDO1_M0/PCIE30X1_1_BUTTON_RSTN/I2C7_SCL_M3/UART8_RTSN_M0/PWM14_M1/SPI0_CS0_M1/CAN1_RX_M1/GPIO4_B2_U (io), AK26 CIF_CLKIN/BT1120_CLKOUT/I2S1_SDI3_M0/PCIE30X2_PERSTN_M1/I2C6_SDA_M3/UART8_TX_M0/SPI2_CS1_M1/GPIO4_B0_D (io), AK27 CIF_D5/BT1120_D5/I2S1_SDI0_M0/PCIE30X1_0_PERSTN_M1/I2C3_SDA_M2/UART3_TX_M2/SPI2_MOSI_M1/GPIO4_A5_D (io), AK30 CIF_D0/BT1120_D0/I2S1_MCLK_M0/PCIE30X1_1_CLKREQN_M1/UART9_RTSN_M1/SPI0_MISO_M1/GPIO4_A0_D (io), AL24 MIPI_CAMERA0_CLK_M0/SPDIF1_TX_M1/I2S1_SDO0_M0/PCIE30X1_0_BUTTON_RSTN/SATA2_ACT_LED_M0/I2C6_SCL_M3/UART8_RX_M0/SPI0_CS1_M1/GPIO4_B1_U (io), AL26 CIF_CLKOUT/BT1120_D10/I2S1_SDO3_M0/PCIE30X4_CLKREQN_M1/DP0_HPDIN_M0/SPDIF0_TX_M1/UART9_TX_M1/PWM11_IR_M1/GPIO4_B4_U (io), AL27 CIF_D6/BT1120_D6/I2S1_SDI1_M0/PCIE30X2_CLKREQN_M1/I2C5_SCL_M2/UART3_RX_M2/SPI2_CLK_M1/GPIO4_A6_D (io), AL28 CIF_D4/BT1120_D4/PCIE30X1_0_WAKEN_M1/I2C3_SCL_M2/UART0_RX_M2/SPI2_MISO_M1/GPIO4_A4_D (io), AL29 CIF_D3/BT1120_D3/PCIE30X1_0_CLKREQN_M1/UART0_TX_M2/GPIO4_A3_D (io), AL30 CIF_D1/BT1120_D1/I2S1_SCLK_M0/PCIE30X1_1_WAKEN_M1/UART9_CTSN_M1/SPI0_MOSI_M1/GPIO4_A1_D (io), AM25 CIF_VSYNC/BT1120_D9/I2S1_SDO2_M0/PCIE20X1_2_BUTTON_RSTN/I2C7_SDA_M3/UART8_CTSN_M0/PWM15_IR_M1/CAN1_TX_M1/GPIO4_B3_U (io), AM27 CIF_D7/BT1120_D7/I2S1_SDI2_M0/PCIE30X2_WAKEN_M1/I2C5_SDA_M2/SPI2_CS0_M1/GPIO4_A7_D (io), AM29 CIF_D2/BT1120_D2/I2S1_LRCK_M0/PCIE30X1_1_PERSTN_M1/SPI0_CLK_M1/GPIO4_A2_D (io)
part K pins: AG9 USB20_HOST0_REXT (in), AG11 USB20_AVDD_1V8 (power), AH9 USB20_HOST1_REXT (in), AH10 USB20_DVDD_0V75 (power), AJ10 USB20_AVDD_3V3 (power), AK6 USB20_HOST0_DP (io), AK8 TYPEC1_USB20_OTG_ID (in), AK9 TYPEC1_USB20_OTG_DP (io), AL6 USB20_HOST0_DM (io), AL7 USB20_HOST1_DP (io), AL8 TYPEC1_USB20_VBUSDET (in), AL9 TYPEC1_USB20_OTG_DM (io), AL12 TYPEC0_USB20_OTG_DP (io), AL14 TYPEC0_USB20_OTG_ID (in), AM7 USB20_HOST1_DM (io), AM12 TYPEC0_USB20_OTG_DM (io), AM14 TYPEC0_USB20_VBUSDET (in), AP7 TYPEC1_USB20_OTG1_REXT (in), AP12 TYPEC0_USB20_OTG0_REXT (in)
part L pins: D28 I2S0_SDI0/GPIO1_D4_D (io), D29 PDM0_CLK0_M0/I2C4_SDA_M4/PWM15_IR_M2/GPIO1_C6_D (io), D30 I2S0_LRCK/I2C2_SCL_M3/UART4_RTSN/GPIO1_C5_D (io), E28 I2S0_SDI1/PDM0_SDI3_M0/I2C1_SDA_M4/UART4_RX_M0/PWM1_M1/SPI1_CS0_M2/GPIO1_D3_D (io), E29 I2S0_SDO0/I2C4_SCL_M4/UART4_CTSN/GPIO1_C7_D (io), E30 PDM0_CLK1_M0/I2C2_SDA_M3/PWM11_IR_M2/SPI4_CS1_M0/GPIO1_C4_D (io), E31 I2S0_SCLK/I2C6_SCL_M1/UART3_CTSN/PWM7_IR_M2/SPI4_CS0_M0/GPIO1_C3_D (io), F26 I2S0_SDO1/I2C7_SCL_M0/UART6_TX_M2/SPI1_MISO_M2/GPIO1_D0_D (io), F27 I2S0_SDO2/I2S0_SDI3/PDM0_SDI1_M0/I2C7_SDA_M0/UART6_RX_M2/SPI1_MOSI_M2/GPIO1_D1_D (io), F28 I2S0_SDO3/I2S0_SDI2/PDM0_SDI2_M0/I2C1_SCL_M4/UART4_TX_M0/PWM0_M1/SPI1_CLK_M2/GPIO1_D2_D (io), F30 I2S0_MCLK/I2C6_SDA_M1/UART3_RTSN/PWM3_IR_M2/SPI4_CLK_M0/GPIO1_C2_D (io), G20 VCCIO1_1V8 (power), G26 PDM0_SDI0_M0/SPI1_CS1_M2/GPIO1_D5_D (io), G27 I2C3_SCL_M0/UART3_TX_M0/SPI4_MOSI_M0/GPIO1_C1_Z (io), G29 I2C3_SDA_M0/UART3_RX_M0/SPI4_MISO_M0/GPIO1_C0_Z (io)
part M pins: AA27 HDMI_TX0_HPD_M1/PCIE30X2_PERSTN_M2/HDMI_RX_HPDOUT_M1/MCU_JTAG_TCK_M1/UART9_RX_M2/SPI0_CS0_M3/GPIO3_D4_D (io), AA28 GMAC1_PTP_REF_CLK/HDMI_TX1_HPD_M1/I2C3_SCL_M1/SPI1_MOSI_M1/GPIO3_B7_D (io), AA29 GMAC1_TXD2/SDIO_D0_M1/I2S3_MCLK/FSPI_D0_M2/I2C6_SDA_M4/PWM10_M0/SPI4_MISO_M1/GPIO3_A0_U (io), AA30 GMAC1_TXD3/SDIO_D1_M1/I2S3_SCLK/AUDDSM_LN/FSPI_D1_M2/I2C6_SCL_M4/PWM11_IR_M0/SPI4_MOSI_M1/GPIO3_A1_U (io), AB28 PCIE30X4_BUTTON_RSTN/DP1_HPDIN_M0/MCU_JTAG_TMS_M1/UART9_TX_M2/PWM11_IR_M3/SPI0_CS1_M3/GPIO3_D5_D (io), AC28 GMAC1_TXD0/I2S2_SDO_M1/UART2_RTSN/GPIO3_B3_U (io), AC29 GMAC1_TXD1/I2S2_MCLK_M1/UART2_CTSN/GPIO3_B4_U (io), AD27 GMAC1_RXD2/SDIO_D2_M1/I2S3_LRCK/AUDDSM_LP/FSPI_D2_M2/UART8_TX_M1/SPI4_CLK_M1/GPIO3_A2_U (io), AD28 GMAC1_TXCLK/SDIO_CMD_M1/I2S3_SDI/AUDDSM_RP/UART8_RTSN_M1/SPI4_CS1_M1/GPIO3_A4_D (io), AD29 GMAC1_TXEN/I2S2_SCLK_M1/CAN1_RX_M0/UART3_TX_M1/PWM12_M0/GPIO3_B5_U (io), AE27 GMAC1_RXD3/SDIO_D3_M1/I2S3_SDO/AUDDSM_RN/FSPI_D3_M2/UART8_RX_M1/SPI4_CS0_M1/GPIO3_A3_U (io), AE28 GMAC1_TXER/I2S2_SDI_M1/UART2_RX_M2/PWM3_IR_M1/GPIO3_B2_D (io), AE29 GMAC1_MCLKINOUT/I2S2_LRCK_M1/CAN1_TX_M0/UART3_RX_M1/PWM13_M0/GPIO3_B6_D (io), AG23 CIF_D13/PCIE20X1_2_PERSTN_M0/HDMI_RX_CEC_M1/UART4_TX_M1/PWM9_M2/SPI0_MISO_M3/GPIO3_D1_D (io), AG24 CIF_D15/PCIE30X2_WAKEN_M2/HDMI_RX_SDA_M1/I2C7_SDA_M2/UART9_CTSN_M2/PWM10_M2/SPI0_CLK_M3/GPIO3_D3_D (io), AG25 CIF_D14/PCIE30X2_CLKREQN_M2/HDMI_RX_SCL_M1/I2C7_SCL_M2/UART9_RTSN_M2/SPI0_MOSI_M3/GPIO3_D2_D (io), AG26 CIF_D10/PCIE30X4_PERSTN_M2/HDMI_TX1_SCL_M1/SPI3_MISO_M3/GPIO3_C6_U (io), AG28 GMAC1_RXD1/MIPI_CAMERA3_CLK_M1/PWM9_M0/GPIO3_B0_U (io), AG29 GMAC1_RXD0/MIPI_CAMERA2_CLK_M1/PWM8_M0/GPIO3_A7_U (io), AH24 CIF_D12/PCIE20X1_2_WAKEN_M0/HDMI_TX0_SDA_M2/I2C5_SDA_M0/UART4_RX_M1/PWM8_M2/SPI3_CLK_M3/GPIO3_D0_U (io), AH25 CIF_D9/FSPI_CS1N_M2/PCIE30X4_WAKEN_M2/HDMI_TX1_SDA_M1/CAN2_TX_M0/UART5_RX_M1/SPI3_CS1_M3/GPIO3_C5_U (io), AH26 CIF_D8/FSPI_CS0N_M2/PCIE30X4_CLKREQN_M2/HDMI_TX1_CEC_M2/CAN2_RX_M0/UART5_TX_M1/SPI3_CS0_M3/GPIO3_C4_U (io), AH27 ETH1_REFCLKO_25M/MIPI_CAMERA1_CLK_M1/I2C4_SCL_M0/GPIO3_A6_D (io), AH29 GMAC1_RXDV_CRS/MIPI_CAMERA4_CLK_M1/UART2_TX_M2/PWM2_M1/GPIO3_B1_D (io), AH30 GMAC1_RXCLK/SDIO_CLK_M1/MIPI_CAMERA0_CLK_M1/FSPI_CLK_M2/I2C4_SDA_M0/UART8_CTSN_M1/GPIO3_A5_D (io), AJ24 CIF_D11/PCIE20X1_2_CLKREQN_M0/HDMI_TX0_SCL_M2/I2C5_SCL_M0/SPI3_MOSI_M3/GPIO3_C7_U (io), W25 VCCIO5_1V8 (power), W26 VCCIO5 (power), Y27 GMAC1_PPSCLK/PCIE30X2_BUTTON_RSTN/UART7_RX_M1/SPI1_CLK_M1/GPIO3_C1_D (io), Y29 GMAC1_PPSTRIG/I2C3_SDA_M1/UART7_TX_M1/SPI1_MISO_M1/GPIO3_C0_D (io), Y30 GMAC1_MDIO/MIPI_TE1/I2C8_SDA_M4/UART7_CTSN_M1/PWM15_IR_M0/SPI1_CS1_M1/GPIO3_C3_D (io), Y31 GMAC1_MDC/MIPI_TE0/I2C8_SCL_M4/UART7_RTSN_M1/PWM14_M0/SPI1_CS0_M1/GPIO3_C2_D (io)
part N pins: G30 PCIE20_2_REFCLKN (io), G31 PCIE20_2_REFCLKP (io), H29 PCIE20_2_TXN/SATA30_2_TXN/USB30_2_SSTXN (out), H30 PCIE20_2_TXP/SATA30_2_TXP/USB30_2_SSTXP (out), H32 PCIE20_1_REFCLKP (io), H33 PCIE20_1_REFCLKN (io), J30 PCIE20_2_RXN/SATA30_2_RXN/USB30_2_SSRXN (in), J31 PCIE20_2_RXP/SATA30_2_RXP/USB30_2_SSRXP (in), J33 PCIE20_1_RXP/SATA30_1_RXP (in), J34 PCIE20_1_RXN/SATA30_1_RXN (in), K27 PCIE20_SATA30_USB30_2_AVDD_1V8 (power), K28 PCIE20_SATA30_USB30_2_AVDD_0V85 (power), K33 PCIE20_1_TXP/SATA30_1_TXP (out), K34 PCIE20_1_TXN/SATA30_1_TXN (out), L27 PCIE20_SATA30_1_AVDD_1V8 (power), L28 PCIE20_SATA30_1_AVDD_0V85 (power), L32 PCIE20_0_REFCLKP (io), L33 PCIE20_0_REFCLKN (io), M27 PCIE20_SATA30_0_AVDD_1V8 (power), M28 PCIE20_SATA30_0_AVDD_0V85 (power), M33 PCIE20_0_TXN/SATA30_0_TXN (out), M34 PCIE20_0_TXP/SATA30_0_TXP (out), N33 PCIE20_0_RXP/SATA30_0_RXP (in), N34 PCIE20_0_RXN/SATA30_0_RXN (in)
part O pins: AG13 TYPEC1_DP1_VDDH_1V8 (power), AG14 TYPEC0_DP0_VDDH_1V8 (power), AG16 TYPEC1_DP1_REXT (in), AH13 TYPEC1_DP1_VDD_0V85 (power), AH14 TYPEC0_DP0_VDDA_0V85 (power), AH16 TYPEC0_DP0_REXT (in), AJ13 TYPEC1_DP1_VDDA_0V85 (power), AJ14 TYPEC0_DP0_VDD_0V85 (power), AL10 TYPEC1_SBU1/DP1_AUXP (io), AL15 TYPEC0_SBU1/DP0_AUXP (io), AM10 TYPEC1_SBU2/DP1_AUXN (io), AM15 TYPEC0_SBU2/DP0_AUXN (io), AN8 TYPEC1_SSRX1P/DP1_TX0P (io), AN9 TYPEC1_SSTX1N/DP1_TX1N (out), AN10 TYPEC1_SSRX2P/DP1_TX2P (io), AN11 TYPEC1_SSTX2N/DP1_TX3N (out), AN13 TYPEC0_SSRX1P/DP0_TX0P (io), AN14 TYPEC0_SSTX1N/DP0_TX1N (out), AN15 TYPEC0_SSRX2P/DP0_TX2P (io), AN16 TYPEC0_SSTX2N/DP0_TX3N (out), AP8 TYPEC1_SSRX1N/DP1_TX0N (io), AP9 TYPEC1_SSTX1P/DP1_TX1P (out), AP10 TYPEC1_SSRX2N/DP1_TX2N (io), AP11 TYPEC1_SSTX2P/DP1_TX3P (out), AP13 TYPEC0_SSRX1N/DP0_TX0N (io), AP14 TYPEC0_SSTX1P/DP0_TX1P (out), AP15 TYPEC0_SSRX2N/DP0_TX2N (io), AP16 TYPEC0_SSTX2P/DP0_TX3P (out)
part P pins: AF19 MIPI_D/C_PHY1_VREG (in), AG19 MIPI_D/C_PHY1_VDD (power), AH19 MIPI_D/C_PHY1_VDD_1V2 (power), AJ19 MIPI_D/C_PHY1_VDD_1V8 (power), AK18 MIPI_DPHY1_RX_D0P/MIPI_CPHY1_RX_TRIO0_B (in), AK19 MIPI_DPHY1_RX_D1P/MIPI_CPHY1_RX_TRIO1_A (in), AK20 MIPI_DPHY1_RX_CLKP/MIPI_CPHY1_RX_TRIO1_C (in), AK21 MIPI_DPHY1_RX_D2P/MIPI_CPHY1_RX_TRIO2_B (in), AK22 MIPI_DPHY1_RX_D3P/NO_USE (in), AL18 MIPI_DPHY1_RX_D0N/MIPI_CPHY1_RX_TRIO0_A (in), AL19 MIPI_DPHY1_RX_D1N/MIPI_CPHY1_RX_TRIO0_C (in), AL20 MIPI_DPHY1_RX_CLKN/MIPI_CPHY1_RX_TRIO1_B (in), AL21 MIPI_DPHY1_RX_D2N/MIPI_CPHY1_RX_TRIO2_A (in), AL22 MIPI_DPHY1_RX_D3N/MIPI_CPHY1_RX_TRIO2_C (in), AN18 MIPI_DPHY1_TX_D0P/MIPI_CPHY1_TX_TRIO0_B (out), AN19 MIPI_DPHY1_TX_D1P/MIPI_CPHY1_TX_TRIO1_A (out), AN20 MIPI_DPHY1_TX_CLKP/MIPI_CPHY1_TX_TRIO1_C (out), AN21 MIPI_DPHY1_TX_D2P/MIPI_CPHY1_TX_TRIO2_B (out), AN22 MIPI_DPHY1_TX_D3P/NO_USE (out), AP18 MIPI_DPHY1_TX_D0N/MIPI_CPHY1_TX_TRIO0_A (out), AP19 MIPI_DPHY1_TX_D1N/MIPI_CPHY1_TX_TRIO0_C (out), AP20 MIPI_DPHY1_TX_CLKN/MIPI_CPHY1_TX_TRIO1_B (out), AP21 MIPI_DPHY1_TX_D2N/MIPI_CPHY1_TX_TRIO2_A (out), AP22 MIPI_DPHY1_TX_D3N/MIPI_CPHY1_TX_TRIO2_C (out)
part Q pins: AD3 OTP_VDDOTP_0V75 (power), AD4 NC (power), AF18 TSADC_TEST_OUT_TS (power), AH18 SARADC_AVDD_1V8 (power), AK15 SARADC_IN5 (in), AK16 SARADC_IN2 (in), AK17 SARADC_IN7 (in), AL16 SARADC_IN1 (in), AL17 SARADC_IN6 (in), AM16 SARADC_IN0_BOOT (in), AM17 SARADC_IN4 (in), AN17 SARADC_IN3 (in)
part R pins: A28 PCIE30_PORT1_REF_CLKP (in), A30 PCIE30_PORT1_TX0N (out), A32 PCIE30_PORT1_RX0N (in), A33 PCIE30_PORT1_RESREF (in), B28 PCIE30_PORT1_REF_CLKN (in), B29 PCIE30_PORT1_TX1N (out), B30 PCIE30_PORT1_TX0P (out), B31 PCIE30_PORT1_RX1N (in), B32 PCIE30_PORT1_RX0P (in), B34 PCIE30_PORT0_RESREF (in), C29 PCIE30_PORT1_TX1P (out), C31 PCIE30_PORT1_RX1P (in), C33 PCIE30_PORT0_TX1P (out), C34 PCIE30_PORT0_TX1N (out), D32 PCIE30_PORT0_TX0P (out), D33 PCIE30_PORT0_TX0N (out), E33 PCIE30_PORT0_REF_CLKP (in), E34 PCIE30_PORT0_REF_CLKN (in), F32 PCIE30_PORT0_RX1P (in), F33 PCIE30_PORT0_RX1N (in), G23 PCIE30_PORT0_AVDD1V8 (power), G24 PCIE30_PORT0_AVDD0V75 (power), G33 PCIE30_PORT0_RX0P (in), G34 PCIE30_PORT0_RX0N (in), H23 PCIE30_PORT1_AVDD1V8 (power), H24 PCIE30_PORT1_AVDD0V75 (power)
part S pins: AA25 MIPI_CSI1_AVCC0V75 (power), AA26 MIPI_CSI1_AVCC1V8 (power), AB25 MIPI_CSI0_AVCC0V75 (power), AB26 MIPI_CSI0_AVCC1V8 (power), AG31 MIPI_CSI1_D0P (in), AG32 MIPI_CSI1_D0N (in), AG33 MIPI_CSI0_D0P (in), AG34 MIPI_CSI0_D0N (in), AH31 MIPI_CSI1_D1P (in), AH32 MIPI_CSI1_D1N (in), AH33 MIPI_CSI0_D1P (in), AH34 MIPI_CSI0_D1N (in), AJ31 MIPI_CSI1_CLK0P (in), AJ32 MIPI_CSI1_CLK0N (in), AJ33 MIPI_CSI0_CLK0P (in), AJ34 MIPI_CSI0_CLK0N (in), AK31 MIPI_CSI1_D2P (in), AK32 MIPI_CSI1_D2N (in), AK33 MIPI_CSI0_D2P (in), AK34 MIPI_CSI0_D2N (in), AL31 MIPI_CSI1_D3P (in), AL32 MIPI_CSI1_D3N (in), AL33 MIPI_CSI0_D3P (in), AL34 MIPI_CSI0_D3N (in), AM31 MIPI_CSI1_CLK1P (in), AM32 MIPI_CSI1_CLK1N (in), AM33 MIPI_CSI0_CLK1P (in), AM34 MIPI_CSI0_CLK1N (in)
part T pins: AF20 MIPI_D/C_PHY0_VREG (in), AG20 MIPI_D/C_PHY0_VDD (power), AH20 MIPI_D/C_PHY0_VDD_1V2 (power), AJ20 MIPI_D/C_PHY0_VDD_1V8 (power), AN24 MIPI_DPHY0_TX_D0P/MIPI_CPHY0_TX_TRIO0_B (out), AN25 MIPI_DPHY0_TX_D1P/MIPI_CPHY0_TX_TRIO1_A (out), AN26 MIPI_DPHY0_TX_CLKP/MIPI_CPHY0_TX_TRIO1_C (out), AN27 MIPI_DPHY0_TX_D2P/MIPI_CPHY0_TX_TRIO2_B (out), AN28 MIPI_DPHY0_TX_D3P/NO_USE (out), AN29 MIPI_DPHY0_RX_D0P/MIPI_CPHY0_RX_TRIO0_B (in), AN30 MIPI_DPHY0_RX_D1P/MIPI_CPHY0_RX_TRIO1_A (in), AN32 MIPI_DPHY0_RX_CLKP/MIPI_CPHY0_RX_TRIO1_C (in), AN33 MIPI_DPHY0_RX_D2P/MIPI_CPHY0_RX_TRIO2_B (in), AN34 MIPI_DPHY0_RX_D3P/NO_USE (in), AP24 MIPI_DPHY0_TX_D0N/MIPI_CPHY0_TX_TRIO0_A (out), AP25 MIPI_DPHY0_TX_D1N/MIPI_CPHY0_TX_TRIO0_C (out), AP26 MIPI_DPHY0_TX_CLKN/MIPI_CPHY0_TX_TRIO1_B (out), AP27 MIPI_DPHY0_TX_D2N/MIPI_CPHY0_TX_TRIO2_A (out), AP28 MIPI_DPHY0_TX_D3N/MIPI_CPHY0_TX_TRIO2_C (out), AP29 MIPI_DPHY0_RX_D0N/MIPI_CPHY0_RX_TRIO0_A (in), AP30 MIPI_DPHY0_RX_D1N/MIPI_CPHY0_RX_TRIO0_C (in), AP31 MIPI_DPHY0_RX_CLKN/MIPI_CPHY0_RX_TRIO1_B (in), AP32 MIPI_DPHY0_RX_D2N/MIPI_CPHY0_RX_TRIO2_A (in), AP33 MIPI_DPHY0_RX_D3N/MIPI_CPHY0_RX_TRIO2_C (in)
part U pins: AA8 AVSS_15 (power), AA10 AVSS_16 (power), AB6 AVSS_17 (power), AB7 AVSS_18 (power), AB8 AVSS_19 (power), AB10 AVSS_20 (power), AC5 AVSS_21 (power), AC8 AVSS_22 (power), AC10 AVSS_23 (power), AD5 AVSS_24 (power), AD8 AVSS_25 (power), AD10 AVSS_26 (power), AE6 AVSS_27 (power), AE7 AVSS_28 (power), AE9 AVSS_29 (power), AF4 AVSS_30 (power), AF7 AVSS_31 (power), AF8 AVSS_32 (power), AF11 AVSS_33 (power), AF12 AVSS_34 (power), AF13 AVSS_35 (power), AF14 AVSS_36 (power), AF15 AVSS_37 (power), AF16 AVSS_38 (power), AF21 AVSS_39 (power), AG3 AVSS_40 (power), AG6 AVSS_41 (power), AG7 AVSS_42 (power), AG10 AVSS_43 (power), AG12 AVSS_44 (power), AG15 AVSS_45 (power), AG18 AVSS_46 (power), AG21 AVSS_47 (power), AG22 AVSS_48 (power), AH4 AVSS_49 (power), AH8 AVSS_50 (power), AH11 AVSS_51 (power), AH12 AVSS_52 (power), AH15 AVSS_53 (power), AH21 AVSS_54 (power), AH22 AVSS_55 (power), AH23 AVSS_56 (power), AJ3 AVSS_57 (power), AJ7 AVSS_58 (power), AJ8 AVSS_59 (power), AJ9 AVSS_60 (power), AJ11 AVSS_61 (power), AJ12 AVSS_62 (power), AJ15 AVSS_63 (power), AJ16 AVSS_64 (power), AJ18 AVSS_65 (power), AJ21 AVSS_66 (power), AJ22 AVSS_67 (power), AJ23 AVSS_68 (power), AK4 AVSS_69 (power), AK5 AVSS_70 (power), AK7 AVSS_71 (power), AK10 AVSS_72 (power), AK11 AVSS_73 (power), AK12 AVSS_74 (power), AK13 AVSS_75 (power), AK14 AVSS_76 (power), AK23 AVSS_77 (power), AL3 AVSS_78 (power), AL4 AVSS_79 (power), AL5 AVSS_80 (power), AL11 AVSS_81 (power), AL13 AVSS_82 (power), AL23 AVSS_83 (power), AM4 AVSS_84 (power), AM8 AVSS_85 (power), AM9 AVSS_86 (power), AM18 AVSS_87 (power), AM20 AVSS_88 (power), AM22 AVSS_89 (power), AM23 AVSS_90 (power), H28 AVSS_1 (power), H31 AVSS_2 (power), J27 AVSS_3 (power), J28 AVSS_4 (power), J29 AVSS_5 (power), J32 AVSS_6 (power), K26 AVSS_7 (power), K31 AVSS_8 (power), K32 AVSS_9 (power), L26 AVSS_10 (power), L31 AVSS_11 (power), M26 AVSS_12 (power), M32 AVSS_13 (power), N32 AVSS_14 (power)
part V pins: AA12 VDD_GPU_MEM_0 (power), AA13 VDD_GPU_0 (power), AA14 VDD_GPU_7 (power), AA15 VDD_GPU_11 (power), AB12 VDD_GPU_MEM_1 (power), AB13 VDD_GPU_1 (power), AB14 VDD_GPU_6 (power), AB15 VDD_GPU_10 (power), AB21 VDD_NPU_6 (power), AB22 VDD_NPU_5 (power), AB23 VDD_NPU_2 (power), AC13 VDD_GPU_2 (power), AC14 VDD_GPU_5 (power), AC15 VDD_GPU_9 (power), AC17 VDD_LOGIC_5 (power), AC18 VDD_LOGIC_4 (power), AC19 VDD_LOGIC_3 (power), AC22 VDD_NPU_4 (power), AC23 VDD_NPU_1 (power), AD13 VDD_GPU_3 (power), AD14 VDD_GPU_4 (power), AD15 VDD_GPU_8 (power), AD17 VDD_LOGIC_0 (power), AD18 VDD_LOGIC_1 (power), AD19 VDD_LOGIC_2 (power), AD22 VDD_NPU_3 (power), AD23 VDD_NPU_0 (power), AE22 VDD_NPU_MEM_0 (power), AE23 VDD_NPU_MEM_1 (power), K19 VDD_LOGIC_8 (power), K20 VDD_LOGIC_9 (power), K23 VDD_CPU_BIG1_9 (power), K24 VDD_CPU_BIG1_0 (power), L23 VDD_CPU_BIG1_8 (power), L24 VDD_CPU_BIG1_1 (power), M16 VDD_CPU_BIG0_0 (power), M17 VDD_CPU_BIG0_9 (power), M19 VDD_CPU_BIG0_MEM_0 (power), M21 VDD_CPU_BIG1_MEM_0 (power), M23 VDD_CPU_BIG1_7 (power), M24 VDD_CPU_BIG1_2 (power), N16 VDD_CPU_BIG0_1 (power), N17 VDD_CPU_BIG0_8 (power), N19 VDD_CPU_BIG0_MEM_1 (power), N21 VDD_CPU_BIG1_MEM_1 (power), N23 VDD_CPU_BIG1_6 (power), N24 VDD_CPU_BIG1_3 (power), P16 VDD_CPU_BIG0_2 (power), P17 VDD_CPU_BIG0_7 (power), P23 VDD_CPU_BIG1_5 (power), P24 VDD_CPU_BIG1_4 (power), R14 VDD_VDENC_0 (power), R16 VDD_CPU_BIG0_3 (power), R17 VDD_CPU_BIG0_6 (power), T14 VDD_VDENC_1 (power), T16 VDD_CPU_BIG0_4 (power), T17 VDD_CPU_BIG0_5 (power), T21 VDD_CPU_LIT_MEM_1 (power), T22 VDD_CPU_LIT_MEM_0 (power), U14 VDD_VDENC_2 (power), U21 VDD_CPU_LIT_7 (power), U22 VDD_CPU_LIT_0 (power), V12 VDD_VDENC_MEM_0 (power), V13 VDD_VDENC_MEM_1 (power), V14 VDD_VDENC_3 (power), V16 VDD_LOGIC_6 (power), V17 VDD_LOGIC_7 (power), V21 VDD_CPU_LIT_6 (power), V22 VDD_CPU_LIT_1 (power), W13 VDD_VDENC_5 (power), W14 VDD_VDENC_4 (power), W21 VDD_CPU_LIT_5 (power), W22 VDD_CPU_LIT_2 (power), Y21 VDD_CPU_LIT_4 (power), Y22 VDD_CPU_LIT_3 (power)
part W pins: A1 VSS_1 (power), A11 VSS_2 (power), A14 VSS_3 (power), A34 VSS_4 (power), B6 VSS_5 (power), B19 VSS_6 (power), B24 VSS_7 (power), B27 VSS_8 (power), B33 VSS_9 (power), C3 VSS_10 (power), C4 VSS_11 (power), C5 VSS_12 (power), C6 VSS_13 (power), C7 VSS_14 (power), C8 VSS_15 (power), C9 VSS_16 (power), C10 VSS_17 (power), C11 VSS_18 (power), C12 VSS_19 (power), C13 VSS_20 (power), C14 VSS_21 (power), C15 VSS_22 (power), C16 VSS_23 (power), C17 VSS_24 (power), C18 VSS_25 (power), C20 VSS_26 (power), C21 VSS_27 (power), C22 VSS_28 (power), C23 VSS_29 (power), C26 VSS_30 (power), C28 VSS_31 (power), C30 VSS_32 (power), C32 VSS_33 (power), D3 VSS_34 (power), D23 VSS_35 (power), D24 VSS_36 (power), D31 VSS_37 (power), E3 VSS_38 (power), E6 VSS_39 (power), E8 VSS_40 (power), E12 VSS_41 (power), E18 VSS_42 (power), E20 VSS_43 (power), E22 VSS_44 (power), E23 VSS_45 (power), E32 VSS_46 (power), F3 VSS_47 (power), F7 VSS_48 (power), F9 VSS_49 (power), F10 VSS_50 (power), F11 VSS_51 (power), F13 VSS_52 (power), F14 VSS_53 (power), F15 VSS_54 (power), F16 VSS_55 (power), F19 VSS_56 (power), F20 VSS_57 (power), F21 VSS_58 (power), F22 VSS_59 (power), F23 VSS_60 (power), F31 VSS_61 (power), G3 VSS_62 (power), G6 VSS_63 (power), G10 VSS_64 (power), G15 VSS_65 (power), G19 VSS_66 (power), G21 VSS_67 (power), G22 VSS_68 (power), G25 VSS_69 (power), G32 VSS_70 (power), H3 VSS_71 (power), H6 VSS_72 (power), H10 VSS_73 (power), H12 VSS_74 (power), H14 VSS_75 (power), H19 VSS_76 (power), H22 VSS_77 (power), H25 VSS_78 (power), H26 VSS_79 (power), J3 VSS_80 (power), J4 VSS_81 (power), J5 VSS_82 (power), J6 VSS_83 (power), J10 VSS_84 (power), J11 VSS_85 (power), J12 VSS_86 (power), J13 VSS_87 (power), J14 VSS_88 (power), J15 VSS_89 (power), J16 VSS_90 (power), J18 VSS_91 (power), J19 VSS_92 (power), J20 VSS_93 (power), J21 VSS_94 (power)
part X pins: J22 VSS_95 (power), J23 VSS_96 (power), J24 VSS_97 (power), J25 VSS_98 (power), K3 VSS_99 (power), K6 VSS_100 (power), K8 VSS_101 (power), K9 VSS_102 (power), K18 VSS_103 (power), K21 VSS_104 (power), K22 VSS_105 (power), L1 VSS_106 (power)
part Y pins: L3 VSS_107 (power), L6 VSS_108 (power), L9 VSS_109 (power), L19 VSS_110 (power), L20 VSS_111 (power), L21 VSS_112 (power), L22 VSS_113 (power), L25 VSS_114 (power), M3 VSS_115 (power), M6 VSS_116 (power), M9 VSS_117 (power), M14 VSS_118 (power), M15 VSS_119 (power), M18 VSS_120 (power), M20 VSS_121 (power), M22 VSS_122 (power), M25 VSS_123 (power), N3 VSS_124 (power), N6 VSS_125 (power), N9 VSS_126 (power), N11 VSS_127 (power), N14 VSS_128 (power), N15 VSS_129 (power), N18 VSS_130 (power), N20 VSS_131 (power), N22 VSS_132 (power), N25 VSS_133 (power), N26 VSS_134 (power), N29 VSS_135 (power), P1 VSS_136 (power), P3 VSS_137 (power), P6 VSS_138 (power), P8 VSS_139 (power), P9 VSS_140 (power), P11 VSS_141 (power), P14 VSS_142 (power), P15 VSS_143 (power), P18 VSS_144 (power), P19 VSS_145 (power), P20 VSS_146 (power), P21 VSS_147 (power), P22 VSS_148 (power), P25 VSS_149 (power), P26 VSS_150 (power), P34 VSS_151 (power), R3 VSS_152 (power), R5 VSS_153 (power), R8 VSS_154 (power), R9 VSS_155 (power), R11 VSS_156 (power), R13 VSS_157 (power), R15 VSS_158 (power), R18 VSS_159 (power), R19 VSS_160 (power), R20 VSS_161 (power), R21 VSS_162 (power), R22 VSS_163 (power), R23 VSS_164 (power), R24 VSS_165 (power), R25 VSS_166 (power), R26 VSS_167 (power), R28 VSS_168 (power), R33 VSS_169 (power), T3 VSS_170 (power), T6 VSS_171 (power), T9 VSS_172 (power), T11 VSS_173 (power), T13 VSS_174 (power), T15 VSS_175 (power), T18 VSS_176 (power), T19 VSS_177 (power), T20 VSS_178 (power), T23 VSS_179 (power)
part Z pins: AA9 HDMI/EDP_TX0_VDD_0V75 (power), AB9 HDMI/EDP_TX0_AVDD_0V75 (power), AC6 HDMI/EDP_TX0_VDD_CMN_1V8 (power), AC7 HDMI/EDP_TX0_VDD_IO_1V8 (power), AC9 HDMI/EDP_TX1_AVDD_0V75 (power), AD6 HDMI/EDP_TX1_VDD_CMN_1V8 (power), AD7 HDMI/EDP_TX1_VDD_IO_1V8 (power), AD9 HDMI/EDP_TX1_VDD_0V75 (power), AG1 HDMI_TX0_SBDN/EDP_TX0_AUXN (io), AG2 HDMI_TX0_SBDP/EDP_TX0_AUXP (io), AH2 HDMI_TX0_D3N/EDP_TX0_D3N (out), AH3 HDMI_TX0_D3P/EDP_TX0_D3P (out), AJ1 HDMI_TX0_D0N/EDP_TX0_D0N (out), AJ2 HDMI_TX0_D0P/EDP_TX0_D0P (out), AK2 HDMI_TX0_D1N/EDP_TX0_D1N (out), AK3 HDMI_TX0_D1P/EDP_TX0_D1P (out), AL1 HDMI_TX0_D2N/EDP_TX0_D2N (out), AL2 HDMI_TX0_D2P/EDP_TX0_D2P (out), AM2 HDMI/EDP_TX0_REXT (in), AM3 HDMI_TX1_D3P/EDP_TX1_D3P (out), AM5 HDMI_TX1_D1P/EDP_TX1_D1P (out), AN1 HDMI/EDP_TX1_REXT (in), AN2 HDMI_TX1_SBDP/EDP_TX1_AUXP (io), AN3 HDMI_TX1_D3N/EDP_TX1_D3N (out), AN4 HDMI_TX1_D0P/EDP_TX1_D0P (out), AN5 HDMI_TX1_D1N/EDP_TX1_D1N (out), AN6 HDMI_TX1_D2P/EDP_TX1_D2P (out), AP2 HDMI_TX1_SBDN/EDP_TX1_AUXN (io), AP4 HDMI_TX1_D0N/EDP_TX1_D0N (out), AP6 HDMI_TX1_D2N/EDP_TX1_D2N (out)
part 27 pins: T24 VSS_180 (power), T25 VSS_181 (power), T26 VSS_182 (power), T27 VSS_183 (power), T33 VSS_184 (power), U3 VSS_185 (power), U12 VSS_186 (power), U13 VSS_187 (power), U15 VSS_188 (power), U16 VSS_189 (power), U17 VSS_190 (power), U20 VSS_191 (power), U23 VSS_192 (power), U24 VSS_193 (power), U30 VSS_194 (power), U31 VSS_195 (power), U34 VSS_196 (power), V3 VSS_197 (power), V4 VSS_198 (power), V5 VSS_199 (power), V8 VSS_200 (power), V9 VSS_201 (power), V10 VSS_202 (power), V11 VSS_203 (power), V15 VSS_204 (power), V18 VSS_205 (power), V19 VSS_206 (power), V23 VSS_207 (power), V24 VSS_208 (power), V25 VSS_209 (power), V27 VSS_210 (power), V30 VSS_211 (power), W2 VSS_212 (power)
part 28 pins: AA3 VSS_248 (power), AA6 VSS_249 (power), AA11 VSS_250 (power), AA16 VSS_251 (power), AA17 VSS_252 (power), AA18 VSS_253 (power), AA19 VSS_254 (power), AA20 VSS_255 (power), AA21 VSS_256 (power), AA22 VSS_257 (power), AA23 VSS_258 (power), AA24 VSS_259 (power), AA31 VSS_260 (power), AB3 VSS_261 (power), AB5 VSS_262 (power), AB11 VSS_263 (power), AB16 VSS_264 (power), AB17 VSS_265 (power), AB18 VSS_266 (power), AB19 VSS_267 (power), AB20 VSS_268 (power), AB24 VSS_269 (power), AB27 VSS_270 (power), W3 VSS_213 (power), W6 VSS_214 (power), W7 VSS_215 (power), W9 VSS_216 (power), W10 VSS_217 (power), W11 VSS_218 (power), W12 VSS_219 (power), W15 VSS_220 (power), W16 VSS_221 (power), W17 VSS_222 (power), W18 VSS_223 (power), W19 VSS_224 (power), W20 VSS_225 (power), W23 VSS_226 (power), W24 VSS_227 (power), W27 VSS_228 (power), Y3 VSS_229 (power), Y5 VSS_230 (power), Y6 VSS_231 (power), Y8 VSS_232 (power), Y9 VSS_233 (power), Y10 VSS_234 (power), Y11 VSS_235 (power), Y12 VSS_236 (power), Y13 VSS_237 (power), Y14 VSS_238 (power), Y15 VSS_239 (power), Y16 VSS_240 (power), Y17 VSS_241 (power), Y18 VSS_242 (power), Y19 VSS_243 (power), Y20 VSS_244 (power), Y23 VSS_245 (power), Y24 VSS_246 (power), Y28 VSS_247 (power)
part 29 pins: AB29 VSS_271 (power), AB32 VSS_272 (power), AC3 VSS_273 (power), AC4 VSS_274 (power), AC11 VSS_275 (power), AC12 VSS_276 (power), AC16 VSS_277 (power), AC20 VSS_278 (power), AC21 VSS_279 (power), AC24 VSS_280 (power), AC27 VSS_281 (power), AD11 VSS_282 (power), AD12 VSS_283 (power), AD16 VSS_284 (power), AD20 VSS_285 (power), AD21 VSS_286 (power), AD24 VSS_287 (power), AD25 VSS_288 (power), AD26 VSS_289 (power), AE3 VSS_290 (power), AE11 VSS_291 (power), AE12 VSS_292 (power), AE13 VSS_293 (power), AE14 VSS_294 (power), AE15 VSS_295 (power), AE16 VSS_296 (power), AE18 VSS_297 (power), AE19 VSS_298 (power), AE20 VSS_299 (power), AE21 VSS_300 (power), AE24 VSS_301 (power), AE26 VSS_302 (power), AF22 VSS_303 (power), AF24 VSS_304 (power), AF25 VSS_305 (power), AF27 VSS_306 (power), AF28 VSS_307 (power), AF29 VSS_308 (power), AF30 VSS_309 (power), AF31 VSS_310 (power), AF32 VSS_311 (power), AG30 VSS_312 (power), AJ30 VSS_313 (power), AK28 VSS_314 (power), AK29 VSS_315 (power), AL25 VSS_316 (power), AM30 VSS_317 (power)
part 30 pins: AM24 AVSS_91 (power), AM26 AVSS_92 (power), AM28 AVSS_93 (power), AN7 AVSS_94 (power), AN12 AVSS_95 (power), AN23 AVSS_96 (power), AN31 AVSS_97 (power), AP1 AVSS_98 (power), AP17 AVSS_99 (power), AP23 AVSS_100 (power), AP34 AVSS_101 (power)

## RP2350A
designator U?
footprint QFN-60_L7.0-W7.0-P0.40-TL-EP3.4
pins: 1 IOVDD, 2 GPIO0, 3 GPIO1, 4 GPIO2, 5 GPIO3, 6 DVDD, 7 GPIO4, 8 GPIO5, 9 GPIO6, 10 GPIO7, 11 IOVDD, 12 GPIO8, 13 GPIO9, 14 GPIO10, 15 GPIO11, 16 GPIO12, 17 GPIO13, 18 GPIO14, 19 GPIO15, 20 IOVDD, 21 XIN, 22 XOUT, 23 DVDD, 24 SWCLK, 25 SWDIO, 26 RUN, 27 GPIO16, 28 GPIO17, 29 GPIO18, 30 IOVDD, 31 GPIO19, 32 GPIO20, 33 GPIO21, 34 GPIO22, 35 GPIO23, 36 GPIO24, 37 GPIO25, 38 IOVDD, 39 DVDD, 40 GPIO26_ADC0, 41 GPIO27_ADC1, 42 GPIO28_ADC2, 43 GPIO29_ADC3, 44 ADC_AVDD, 45 IOVDD, 46 VREG_AVDD, 47 VREG_PGND, 48 VREG_LX, 49 VREG_VIN, 50 VREG_FB, 51 USB_DM, 52 USB_DP, 53 USB_OTP_VDD, 54 QSPI_IOVDD, 55 QSPI_SD3, 56 QSPI_SCLK, 57 QSPI_SD0, 58 QSPI_SD2, 59 QSPI_SD1, 60 QSPI_SS, 61 GND

## RSMT0215
designator R?, comment value 100k  (hidden comment: Resistor)
Manufacturer 1: TE Connectivity; Manufacturer Part Number 1: 1622827-1; MCHP-ID: RSMT0215; Tolerance: 1%; Description_: RES TKF 100k 1% 1/10W SMD 0603; Dev Tools Status: Production; Voltage: 75V; Power: 1/10W; Populated: YES; Owner: Cristian Papuc; Temperature Coefficient: 100ppm/C; Restricted Sourcing: No
footprint RES_C_0603
pins: 1, 2
2 alternate drawings of the same symbol

## RSMT1019
designator R?, comment value 10k  (hidden comment: Resistor)
Manufacturer 1: Panasonic; Manufacturer Part Number 1: ERJ-2RKF1002X; MCHP-ID: RSMT1019; Tolerance: 1%; Description_: RES TKF 10k 1% 1/10W SMD 0402; Dev Tools Status: Production; Temperature Coeffcient: 100ppm/C; Power: 1/10W; Populated: Yes; Voltage: 50V; Owner: Brent Lanphear
footprint RES_C_0402
pins: 1, 2

## RSMT1019_1
designator R?, comment DNP  value 10k
Manufacturer 1: Panasonic; Manufacturer Part Number 1: ERJ-2RKF1002X; MCHP-ID: RSMT1019; Tolerance: 1%; Symbol: Resistor; Description_: RES TKF 10k 1% 1/10W SMD 0402; Dev Tools Status: Production; Temperature Coeffcient: 100ppm/C; Power: 1/10W; Populated: Yes; Voltage: 50V; Owner: Brent Lanphear
footprint RES_C_0402
pins: 1, 2

## RSMT1040
designator R?, comment value 0R  Populated: DNP  (hidden comment: Resistor)
Manufacturer 1: Yageo; Manufacturer Part Number 1: RC0402JR-070RL; MCHP-ID: RSMT1040; Description_: RES TKF 0R 1/16W SMD 0402; Dev Tools Status: Production; Power: 1/16W; Owner: Sompoch Loboonlert
footprint RES_C_0402
pins: 1, 2

## RSMT1049
designator R?, comment value 15k  Tolerance: 1%  (hidden comment: Resistor)
Manufacturer 1: Stackpole Electronics Inc; Manufacturer Part Number 1: RMCF0603FT15K0; MCHP-ID: RSMT1049; Description_: RES TKF 15k 1% 1/10W SMD 0603; Dev Tools Status: Production; Voltage: 50V; Temperature Coeffcient: 100ppm/C; Current: 1A; Power: 1/10W; Owner: Leah Whitaker; Populated: Yes
footprint RES_C_0603
pins: 1, 2

## RSMT1100
designator R?, comment value 330R  (hidden comment: Resistor)
Manufacturer 1: Yageo; Manufacturer Part Number 1: RC0402FR-07330RL; MCHP-ID: RSMT1100; Tolerance: 1%; Description_: RES TKF 330R 1% 1/16W SMD 0402; Dev Tools Status: Production; Power: 1/16W; Populated: YES; Owner: Mike Ragsdale; Circuit Type: Isolated; Restricted Sourcing: No
footprint RES_C_0402
pins: 1, 2
2 alternate drawings of the same symbol

## SDCW2012-2-900TF
designator U?
footprint FILTER-SMD_4P-L2.0-W1.3-BL_DLW21
pins: 1, 2, 3, 4

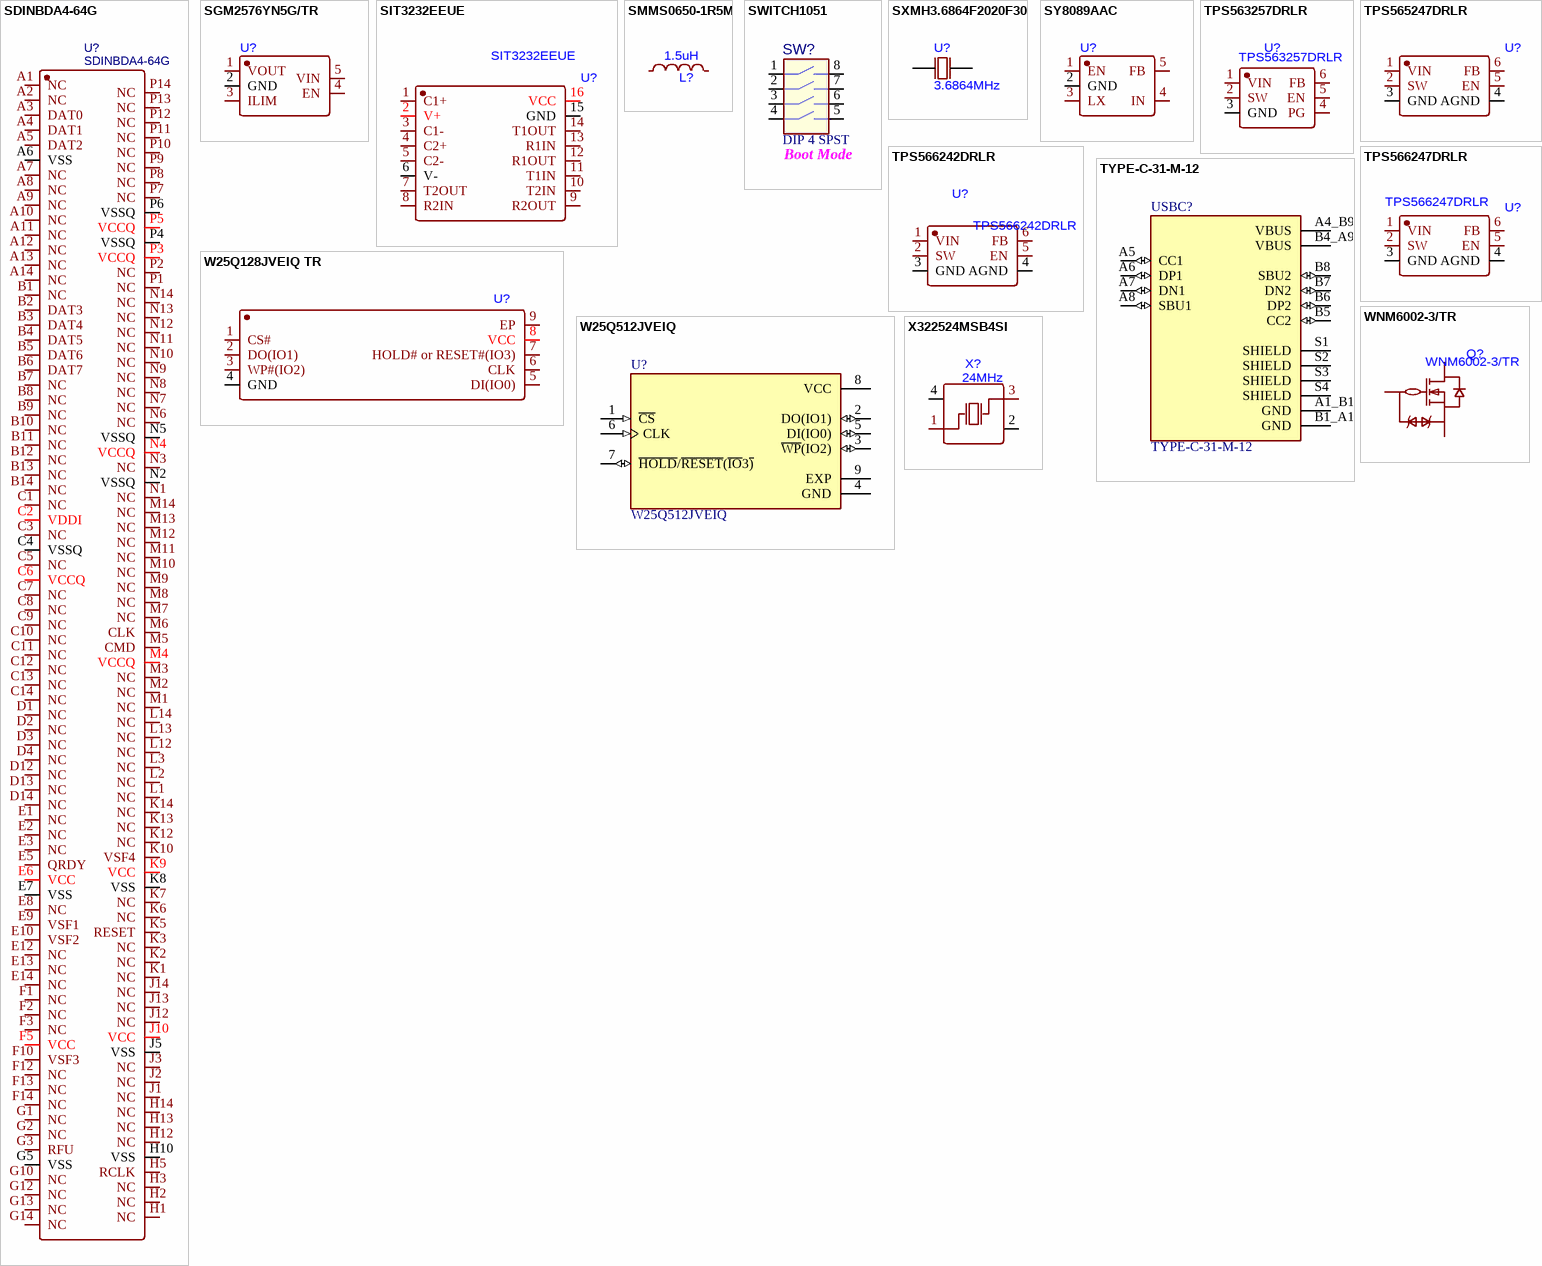
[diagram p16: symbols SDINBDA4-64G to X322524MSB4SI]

## SDINBDA4-64G
designator U?
Manufacturer: SANDISK(闪迪); Contributor: LCSC
footprint FBGA-153_L13.0-W11.5-P0.50_KLMAG1JETD-B041
pins: A1 NC, A2 NC, A3 DAT0, A4 DAT1, A5 DAT2, A6 VSS, A7 NC, A8 NC, A9 NC, A10 NC, A11 NC, A12 NC, A13 NC, A14 NC, B1 NC, B2 DAT3, B3 DAT4, B4 DAT5, B5 DAT6, B6 DAT7, B7 NC, B8 NC, B9 NC, B10 NC, B11 NC, B12 NC, B13 NC, B14 NC, C1 NC, C2 VDDI, C3 NC, C4 VSSQ, C5 NC, C6 VCCQ, C7 NC, C8 NC, C9 NC, C10 NC, C11 NC, C12 NC, C13 NC, C14 NC, D1 NC, D2 NC, D3 NC, D4 NC, D12 NC, D13 NC, D14 NC, E1 NC, E2 NC, E3 NC, E5 QRDY, E6 VCC, E7 VSS, E8 NC, E9 VSF1, E10 VSF2, E12 NC, E13 NC, E14 NC, F1 NC, F2 NC, F3 NC, F5 VCC, F10 VSF3, F12 NC, F13 NC, F14 NC, G1 NC, G2 NC, G3 RFU, G5 VSS, G10 NC, G12 NC, G13 NC, G14 NC, H1 NC, H2 NC, H3 NC, H5 RCLK, H10 VSS, H12 NC, H13 NC, H14 NC, J1 NC, J2 NC, J3 NC, J5 VSS, J10 VCC, J12 NC, J13 NC, J14 NC, K1 NC, K2 NC, K3 NC, K5 RESET, K6 NC, K7 NC, K8 VSS, K9 VCC, K10 VSF4, K12 NC, K13 NC, K14 NC, L1 NC, L2 NC, L3 NC, L12 NC, L13 NC, L14 NC, M1 NC, M2 NC, M3 NC, M4 VCCQ, M5 CMD, M6 CLK, M7 NC, M8 NC, M9 NC, M10 NC, M11 NC, M12 NC, M13 NC, M14 NC, N1 NC, N2 VSSQ, N3 NC, N4 VCCQ, N5 VSSQ, N6 NC, N7 NC, N8 NC, N9 NC, N10 NC, N11 NC, N12 NC, N13 NC, N14 NC, P1 NC, P2 NC, P3 VCCQ, P4 VSSQ, P5 VCCQ, P6 VSSQ, P7 NC, P8 NC, P9 NC, P10 NC, P11 NC, P12 NC, P13 NC, P14 NC

## SGM2576YN5G/TR
designator U?
footprint SOT-23-5_L2.9-W1.6-P0.95-LS2.8-TL
pins: 1 VOUT, 2 GND, 3 ILIM, 4 EN, 5 VIN

## SIT3232EEUE
designator U?
footprint TSSOP-16_L5.0-W4.4-P0.65-LS6.4-BL
pins: 1 C1+, 2 V+, 3 C1-, 4 C2+, 5 C2-, 6 V-, 7 T2OUT, 8 R2IN, 9 R2OUT, 10 T2IN, 11 T1IN, 12 R1OUT, 13 R1IN, 14 T1OUT, 15 GND, 16 VCC

## SMMS0650-1R5M
designator L?, comment 1.5uH
footprint IND-SMD_L7.1-W6.6
pins: 1, 2

## SWITCH1051
designator SW?, comment value DIP 4 SPST  Legend Note: Boot Mode  (hidden comment: Switch DIP 4 Pos)
Switch DIP; Manufacturer 1: Copal Electronics; Manufacturer Part Number 1: CHS-04TB; MCHP-ID: SWITCH1051; Description_: SWITCH DIP 4-POS SLIDE SMD 6V; Dev Tools Status: Production; Populated: YES
footprint SW_SMD_1.27MM X 4 copal
pins: 1, 2, 3, 4, 5, 6, 7, 8

## SXMH3.6864F2020F30
designator U?, comment 3.6864MHz
MN: SXMH3.6864F2020F30
footprint HC-49S_L11.4-W4.5-LS12.5
pins: 1 OSC1, 2 OSC2

## SY8089AAC
designator U?
footprint SOT-23-5_L2.9-W1.6-P0.95-LS2.8-BL
pins: 1 EN, 2 GND, 3 LX, 4 IN, 5 FB

## TPS563257DRLR
designator U?
footprint SOT-666-6_L1.6-W1.2-P0.50-LS1.6-BR
pins: 1 VIN, 2 SW, 3 GND, 4 PG, 5 EN, 6 FB

## TPS565247DRLR
designator U?
footprint SOT-5X3-6_W1.6-L1.2-P0.50-LS1.6-BL
pins: 1 VIN, 2 SW, 3 GND, 4 AGND, 5 EN, 6 FB

## TPS566242DRLR
designator U?
-40℃~+125℃@(TJ) 1 120uA 3V~16V 600kHz 600mV~7V 6A Adjustable Buck Buck Built-in Yes SOT-563 DC-DC Converters ROHS
footprint SOT-666-6_L1.6-W1.2-P0.50-LS1.6-BL
pins: 1 VIN, 2 SW, 3 GND, 4 AGND, 5 EN, 6 FB

## TPS566247DRLR
designator U?
-40℃~+125℃@(TJ) 1 3V~16V 400uA 600kHz 600mV~7V 6A Adjustable Buck Buck Built-in Yes SOT-563 DC-DC Converters ROHS
footprint SOT-5X3-6_W1.6-L1.2-P0.50-LS1.6-BL
pins: 1 VIN, 2 SW, 3 GND, 4 AGND, 5 EN, 6 FB

## TYPE-C-31-M-12
designator USBC?
USB Connectors 24 Receptacle 1 8.94*7.3mm RoHS; MF: HRO Electronics Co., Ltd.
footprint HRO_TYPE-C-31-M-12
pins: A1_B12 GND (power), A4_B9 VBUS (power), A5 CC1 (io), A6 DP1 (io), A7 DN1 (io), A8 SBU1 (io), B1_A12 GND (power), B4_A9 VBUS (power), B5 CC2 (io), B6 DP2 (io), B7 DN2 (io), B8 SBU2 (io), S1 SHIELD, S2 SHIELD, S3 SHIELD, S4 SHIELD

## W25Q128JVEIQ TR
designator U?
footprint WSON-8_L6.0-W8.0-P1.27-BL-EP
pins: 1 CS#, 2 DO(IO1), 3 WP#(IO2), 4 GND, 5 DI(IO0), 6 CLK, 7 HOLD# or RESET#(IO3), 8 VCC, 9 EP

## W25Q512JVEIQ
designator U?
FLASH - NOR Memory IC 512Mb (64M x 8) SPI - Quad I/O 133 MHz 8-WSON (8x6); MF: Winbond Electronics
footprint SON127P600X800X80-9N
pins: 1 ~{CS} (in), 2 DO(IO1) (io), 3 ~{WP}(IO2) (io), 4 GND (power), 5 DI(IO0) (io), 6 CLK (in), 7 ~{HOLD}/~{RESET}(~{IO}3~{)} (io), 8 VCC (power), 9 EXP

## WNM6002-3/TR
designator Q?
footprint SOT-323-3_L2.0-W1.3-P1.30-LS2.1-BR
pins: 1 G, 2 S, 3 D

## X322524MSB4SI
designator X?, comment 24MHz
X322524MSB4SI
footprint CRYSTAL-SMD_4P-L3.2-W2.5-BL
pins: 1 OSC1, 2 GND, 3 OSC2, 4 GND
